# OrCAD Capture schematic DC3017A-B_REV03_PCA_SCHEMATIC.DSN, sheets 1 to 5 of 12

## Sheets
1 POWER SUPPLY: size Custom; company: ANALOG DEVICES; note: DEMO BOARD BILL OF MATERIALS; note: 24-PORT IEEE 802.3bt PSE MOTHER BOARD
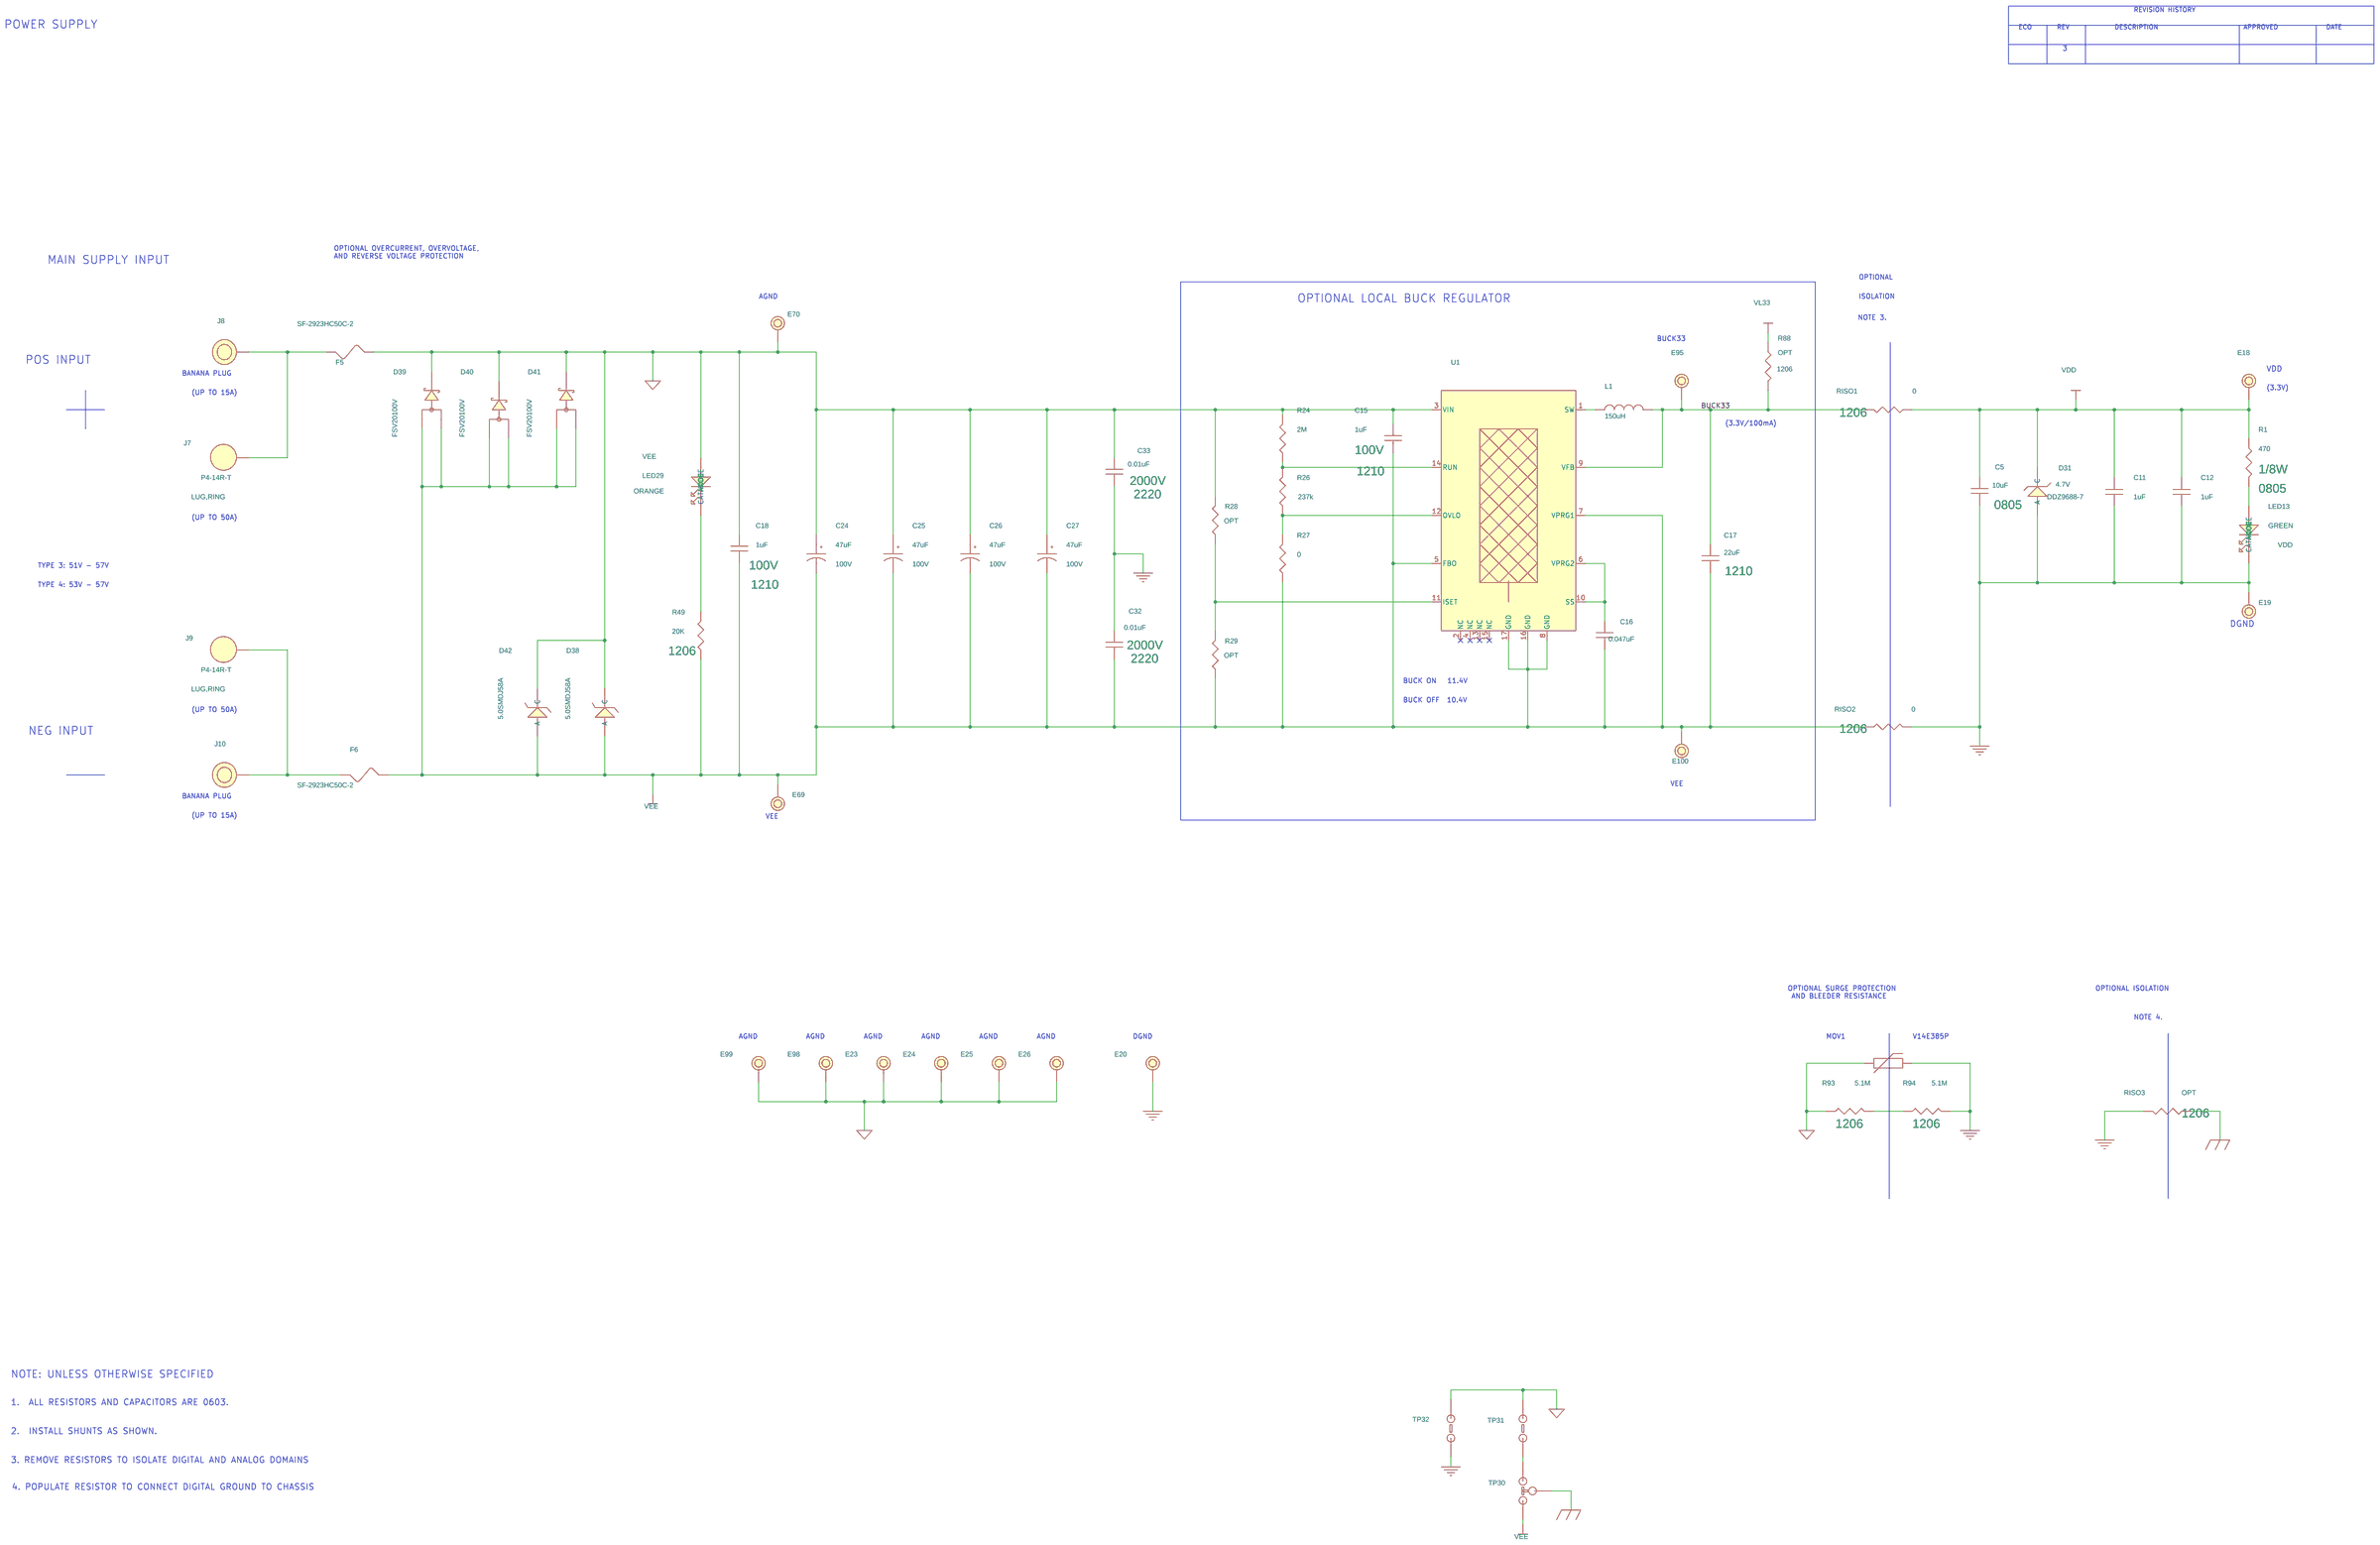
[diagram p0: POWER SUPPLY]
2 CONFIGURATIONS: size Custom
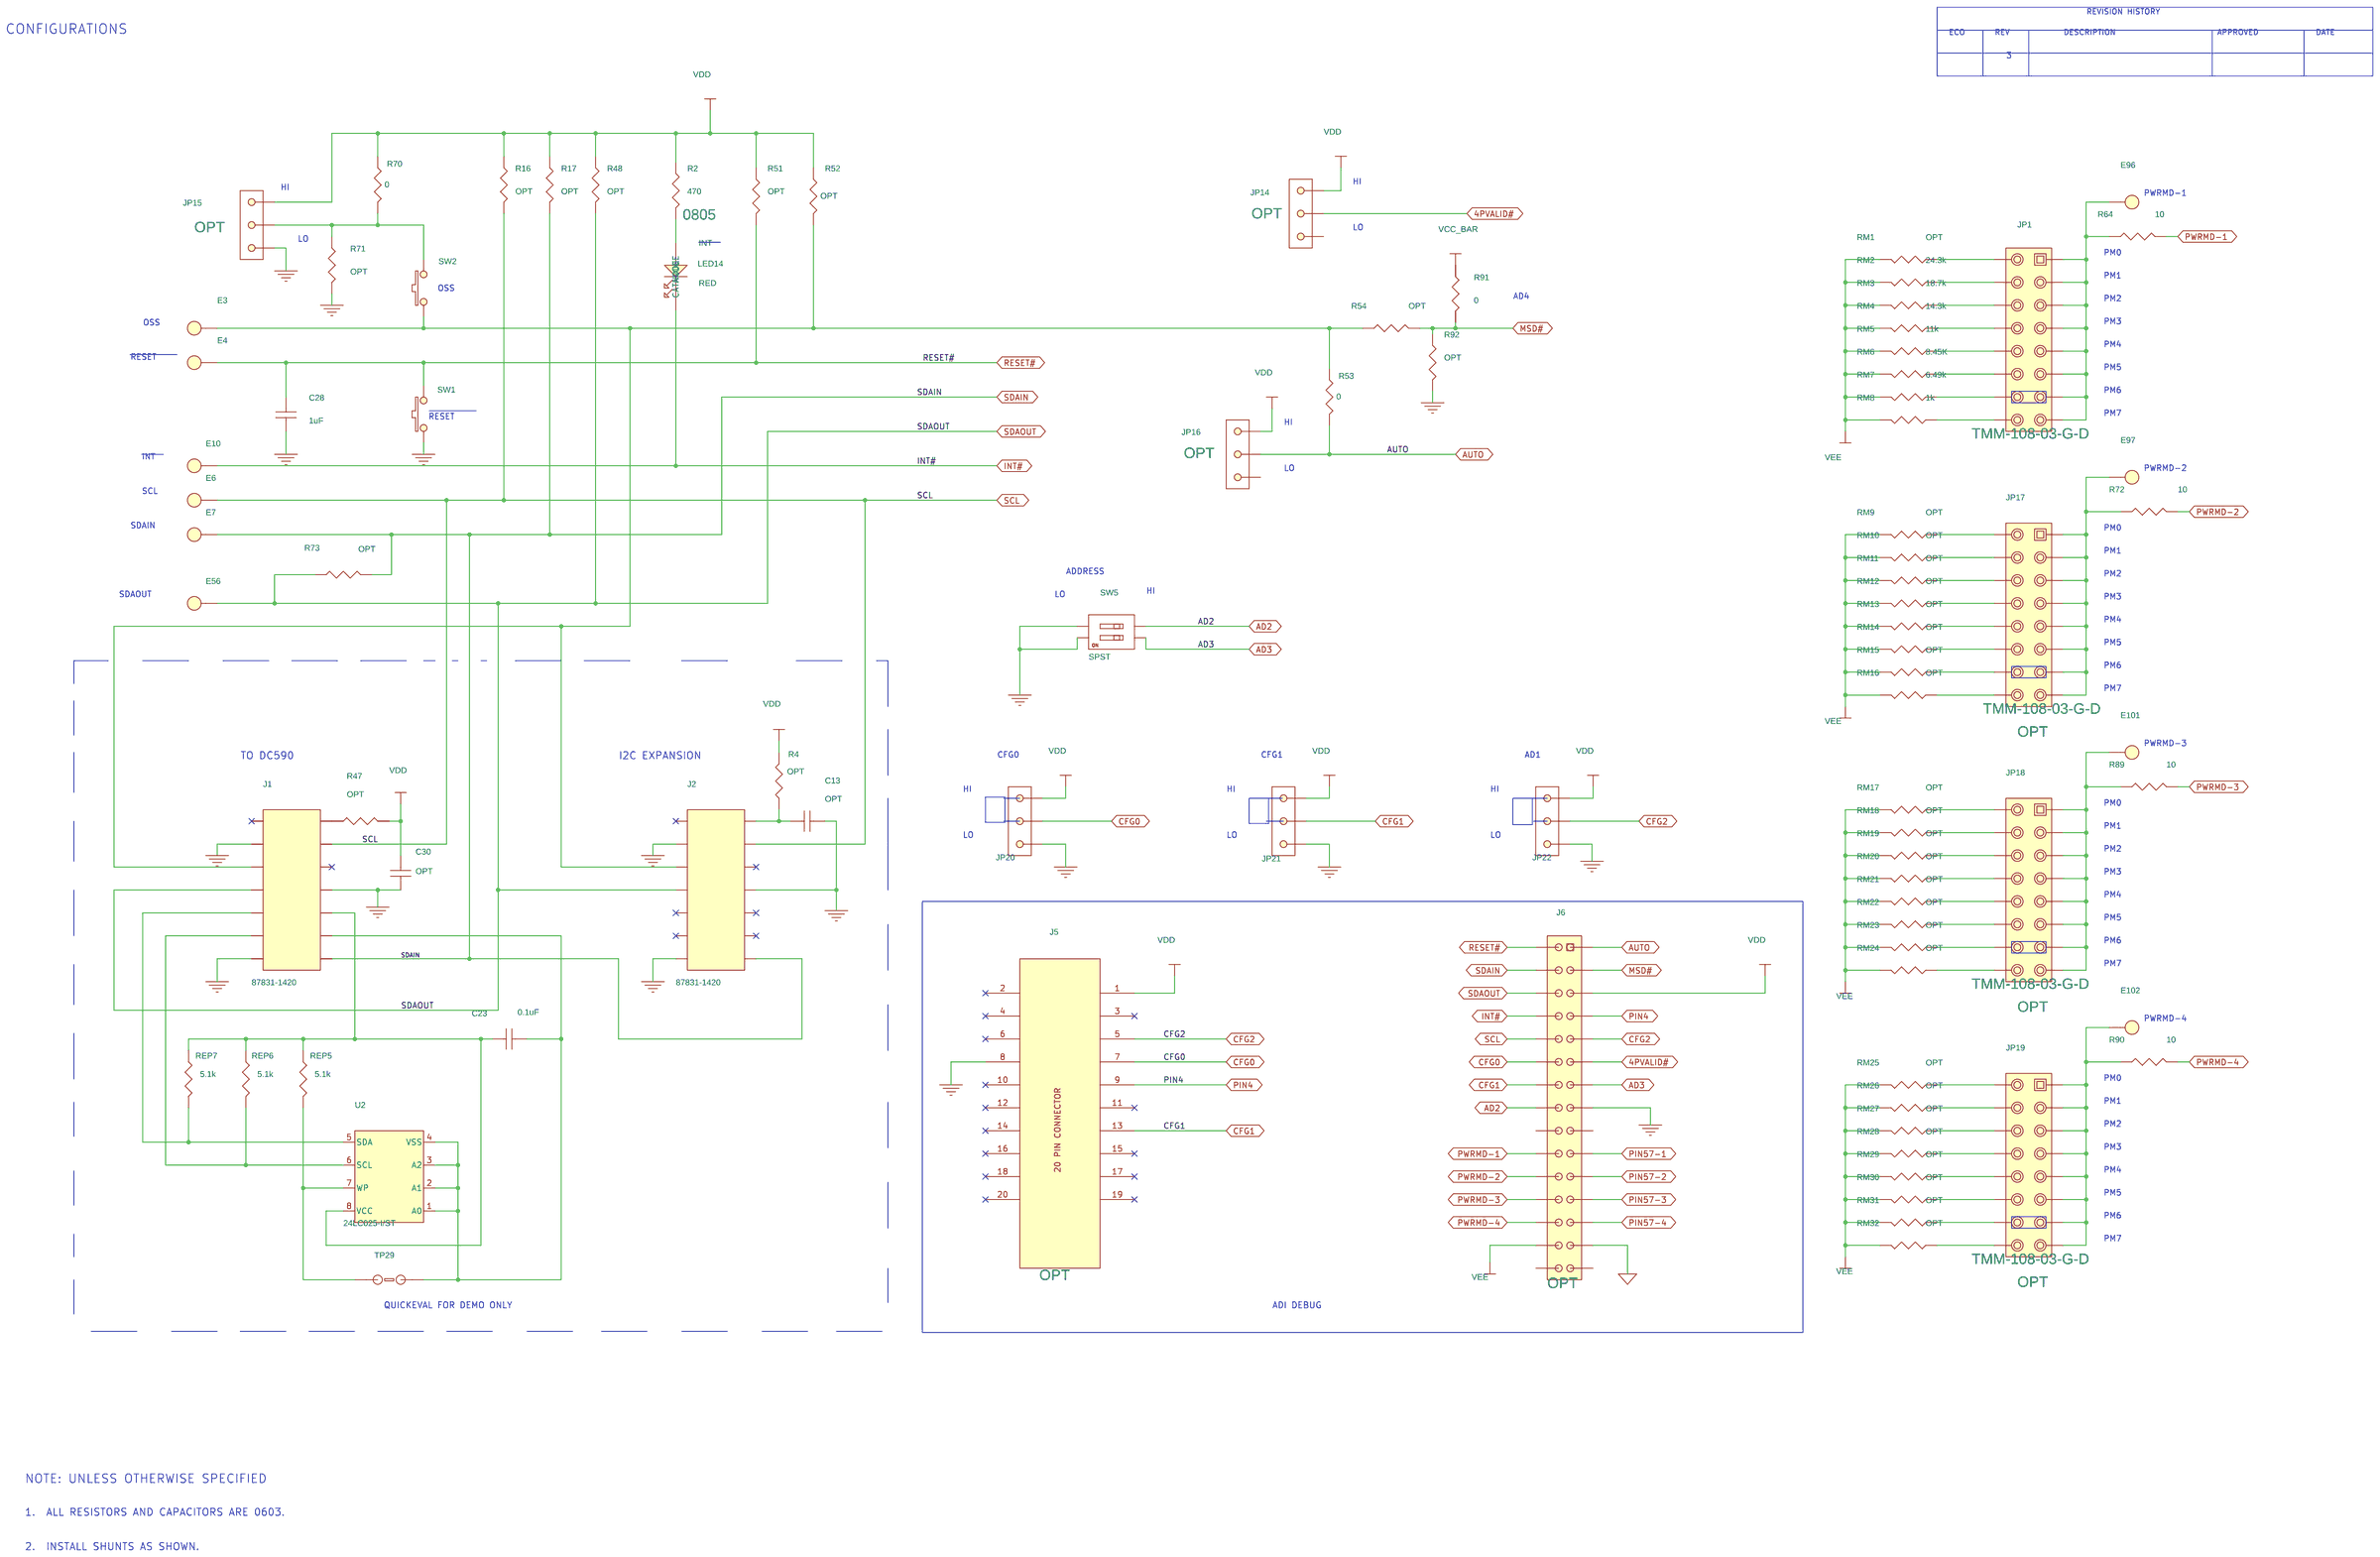
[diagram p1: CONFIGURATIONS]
3 DAUGHTER CARD CONNECTIONS: size Custom
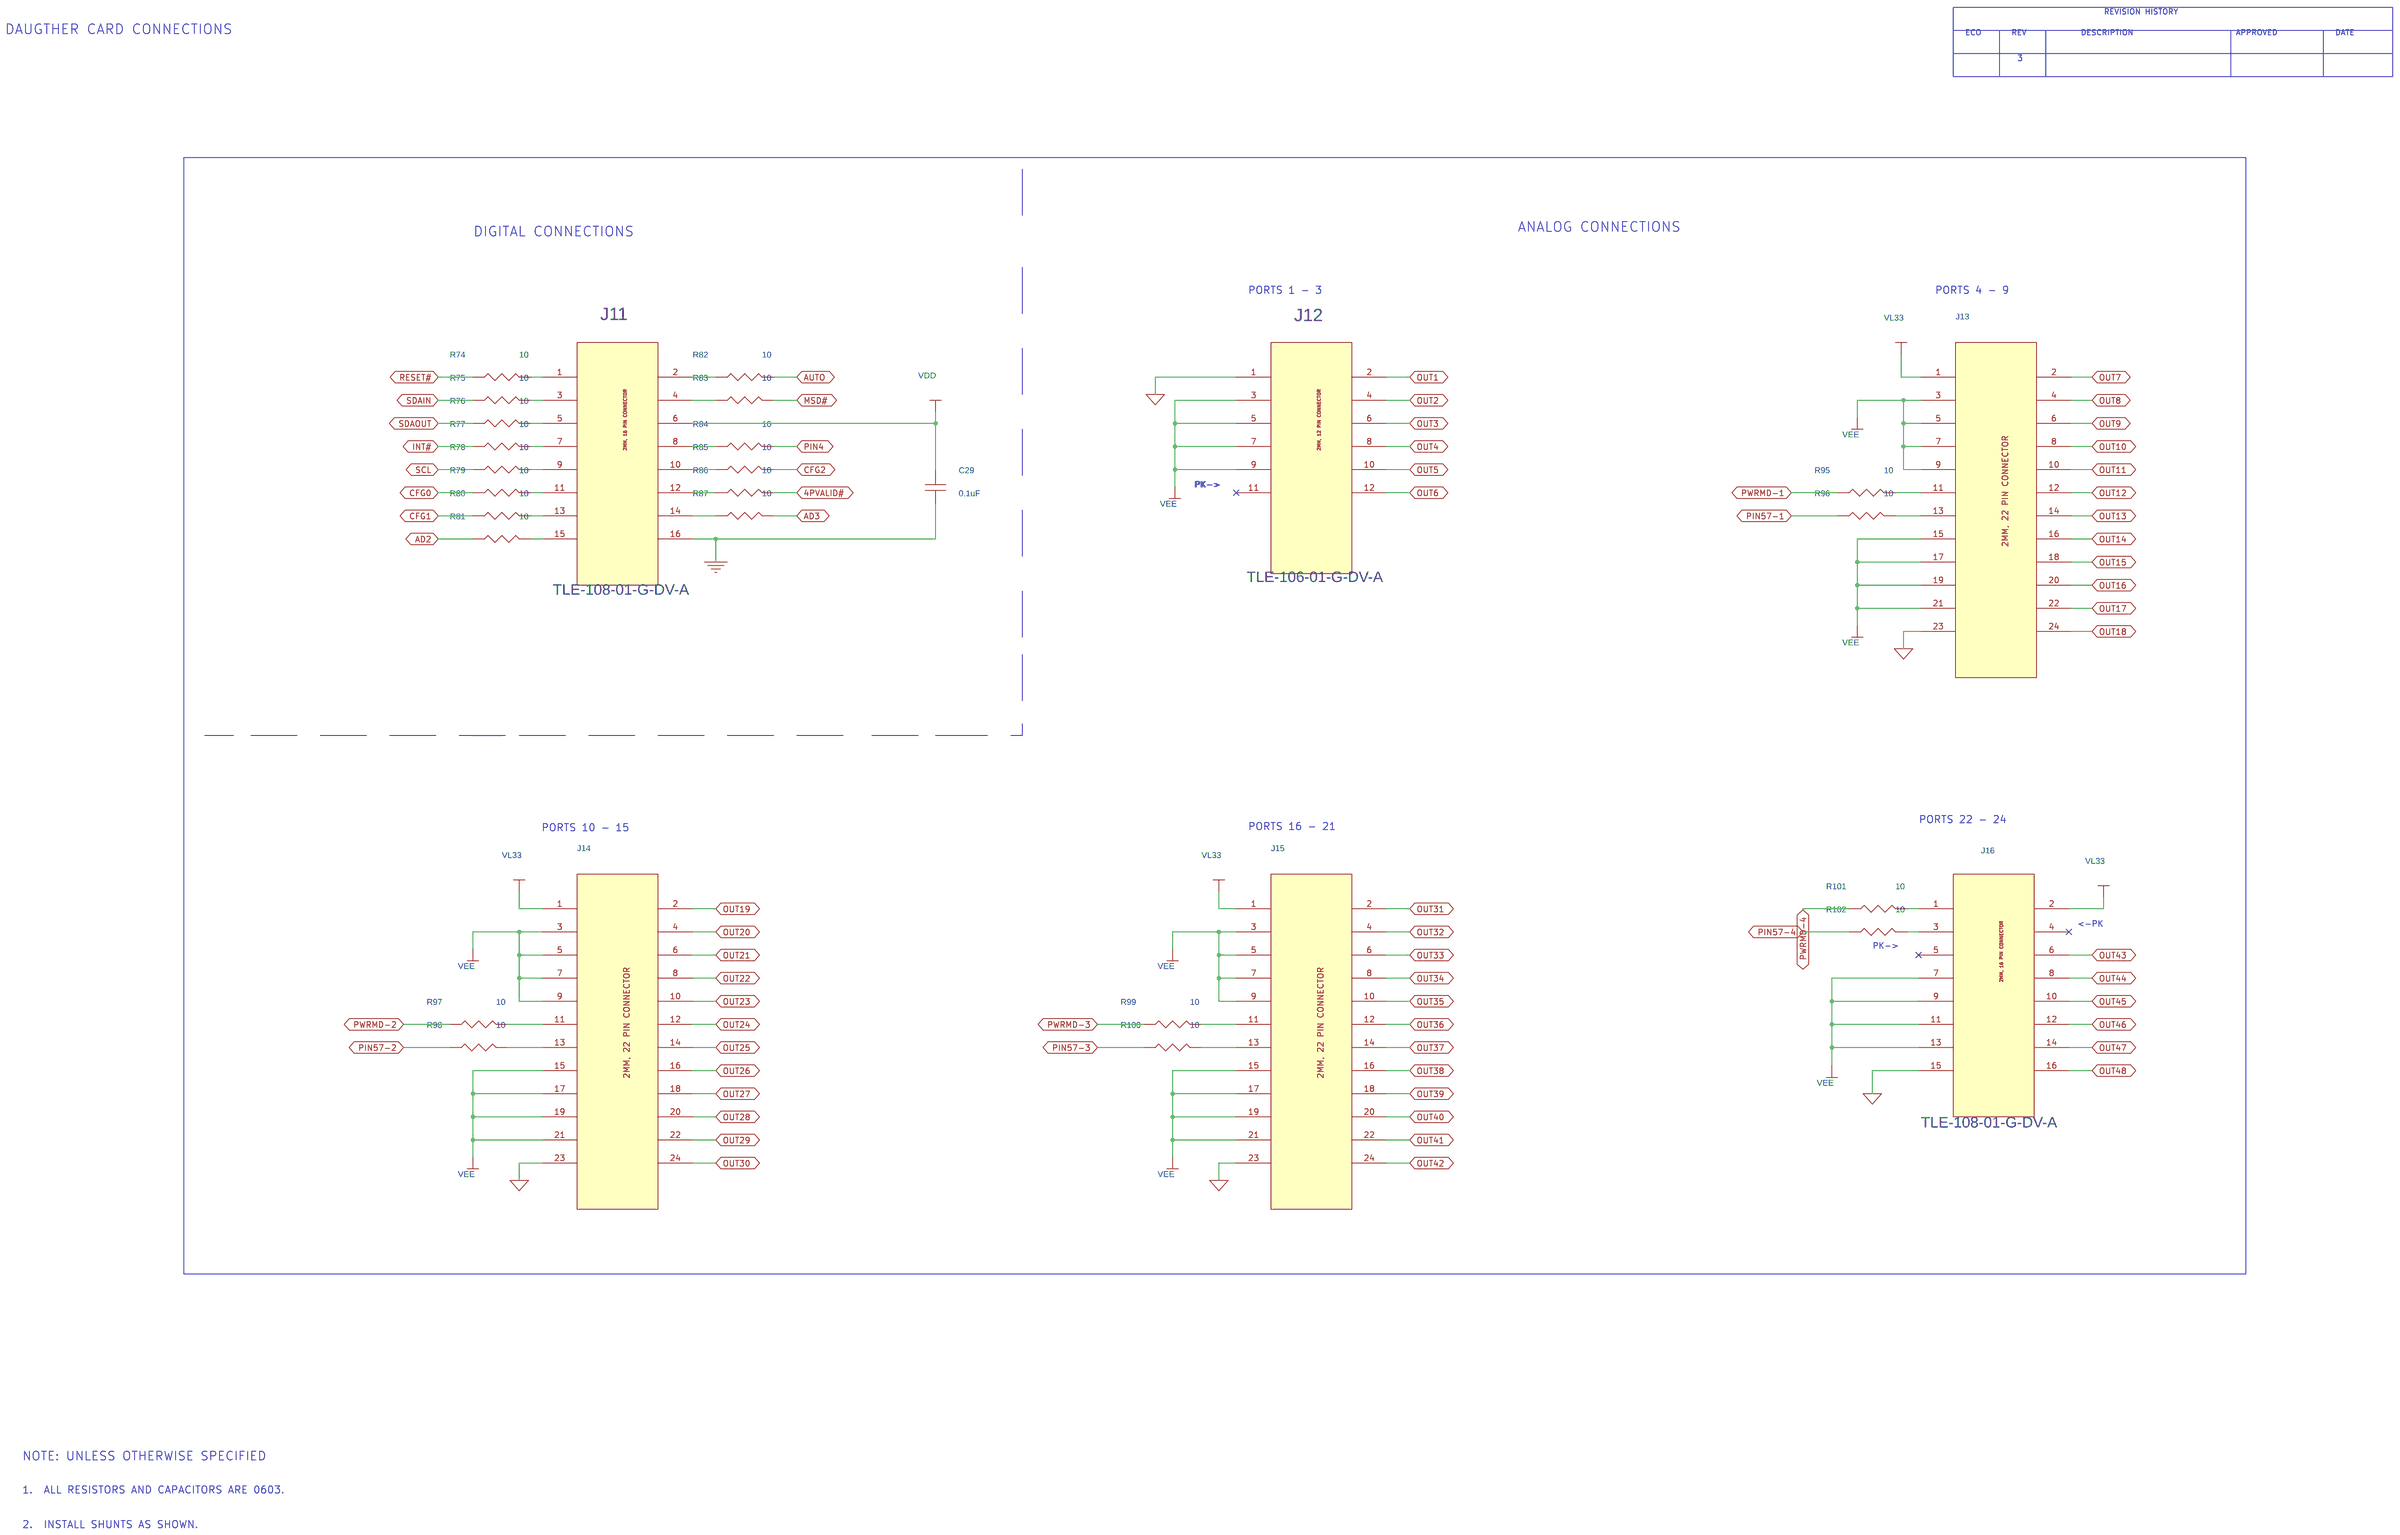
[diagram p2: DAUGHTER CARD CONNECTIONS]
4 PORTS 1-4: size Custom
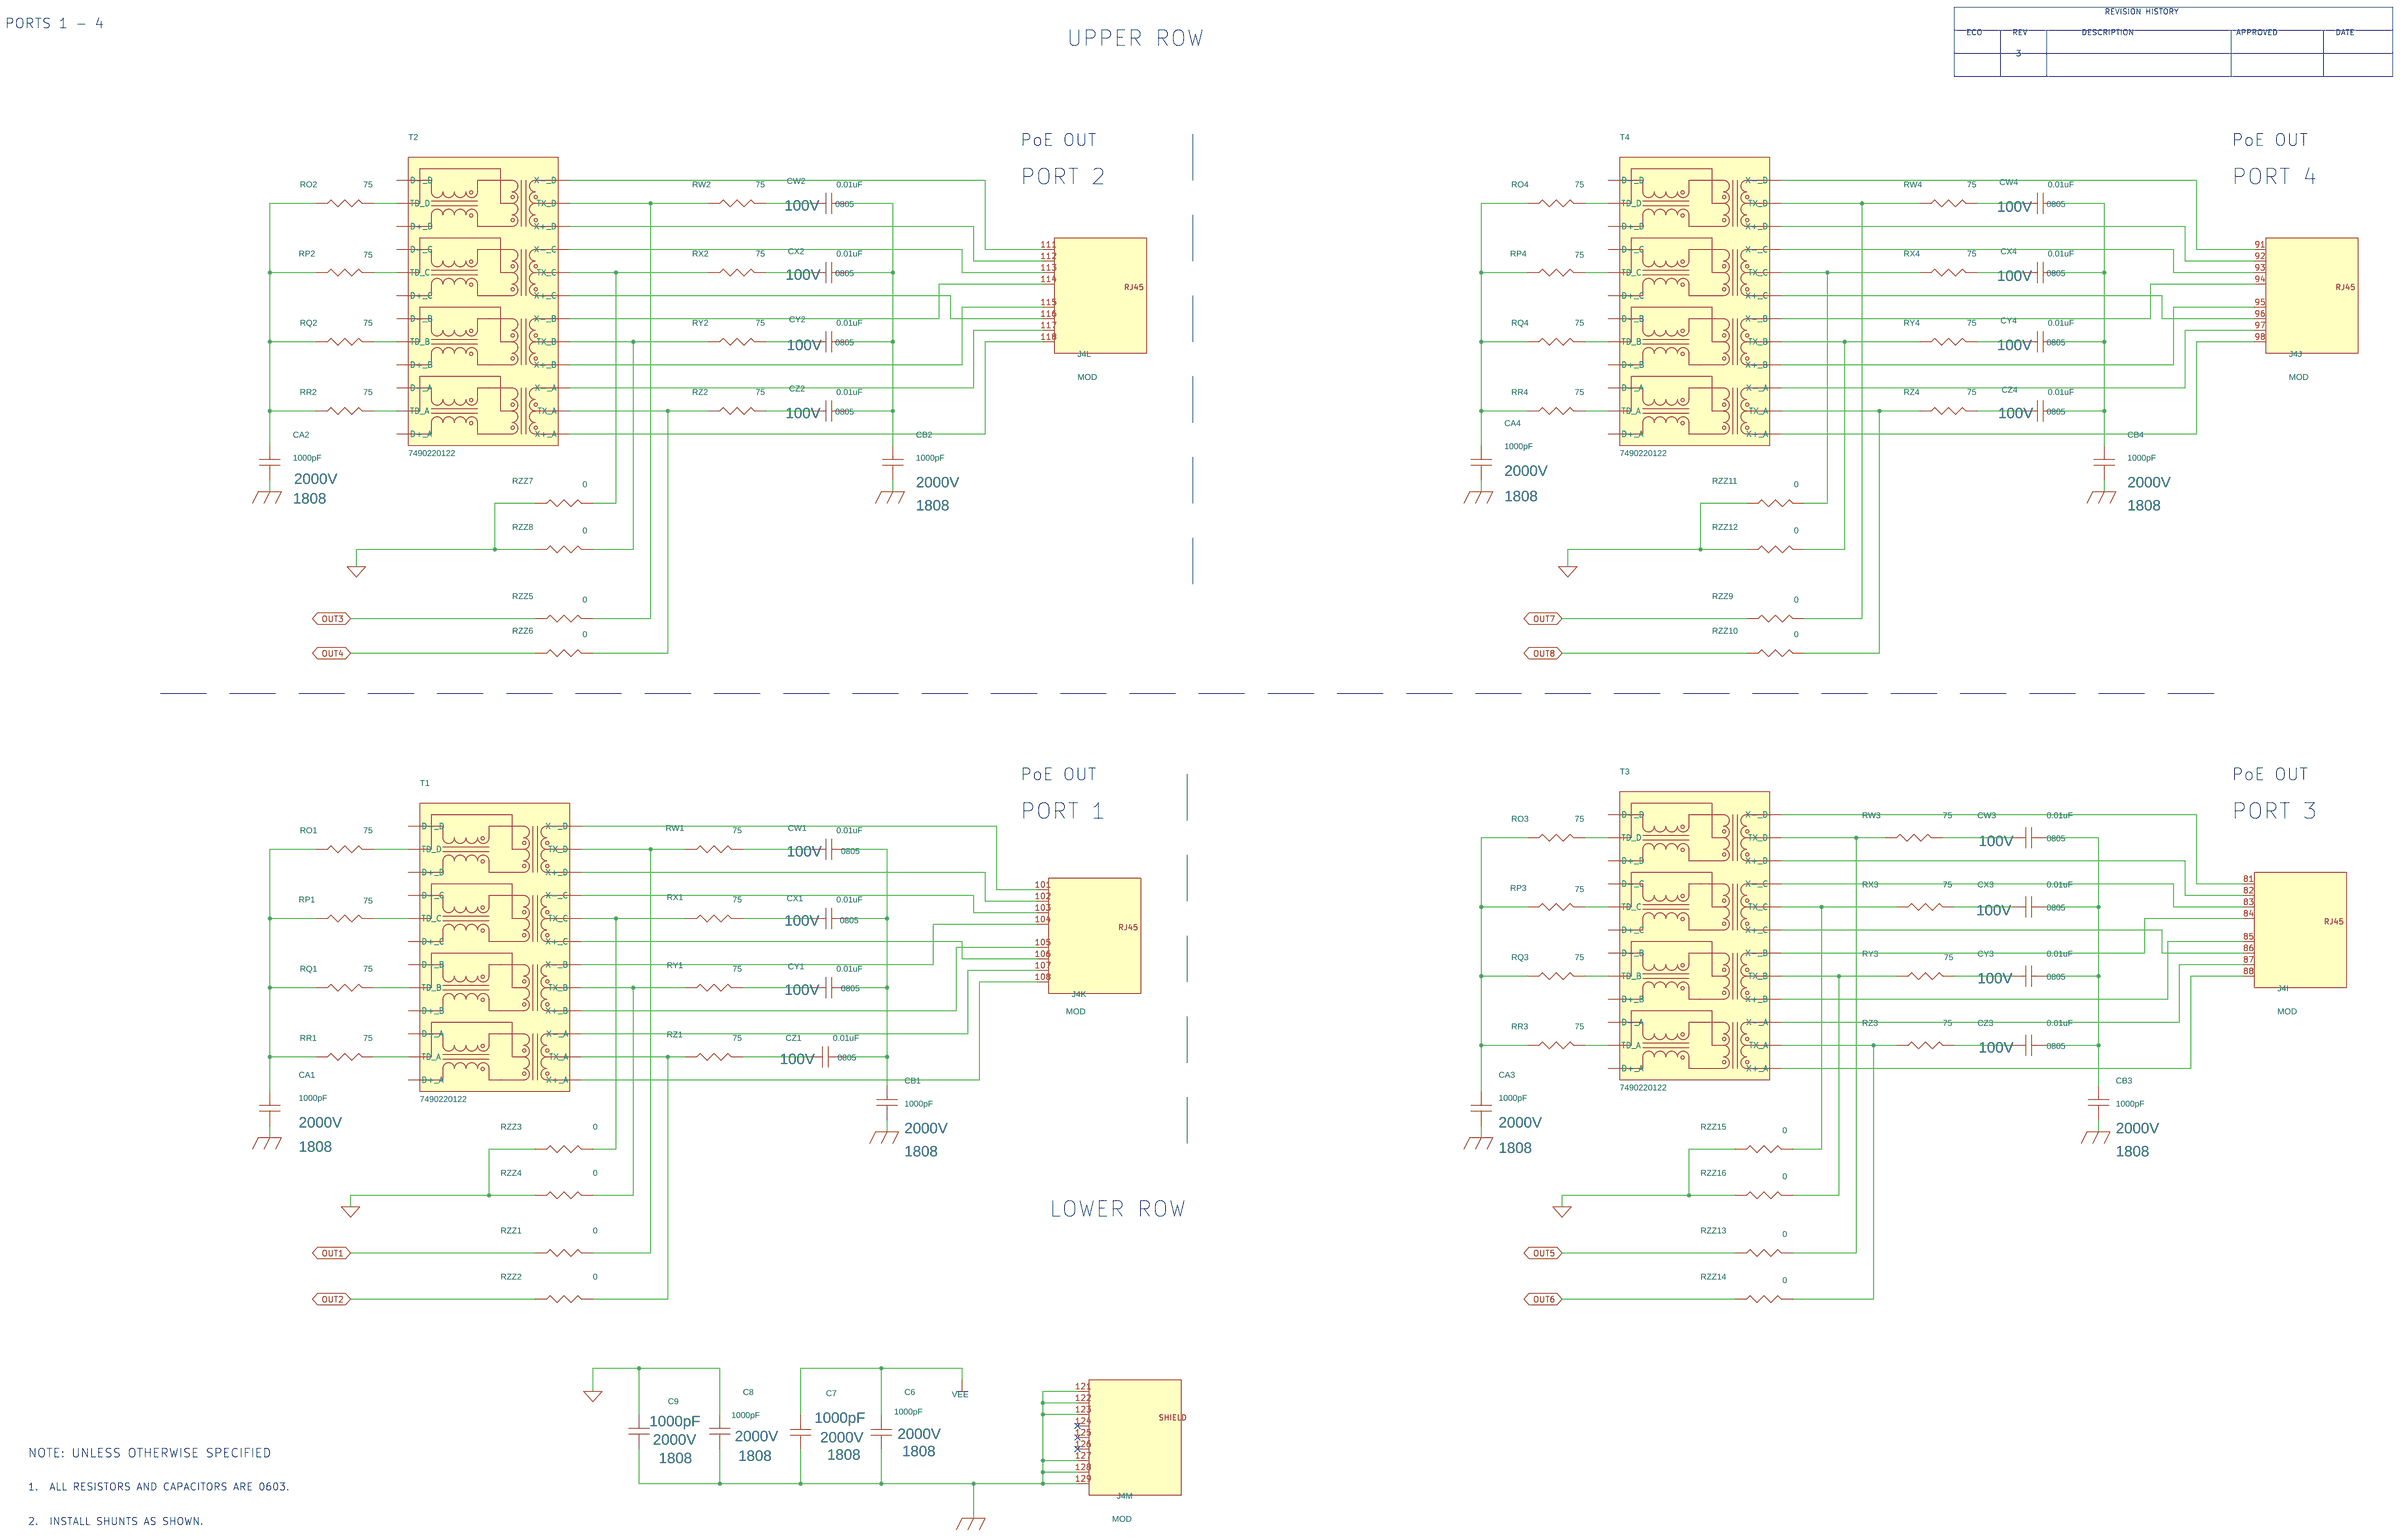
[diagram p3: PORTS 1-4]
5 PORTS 5-8: size Custom
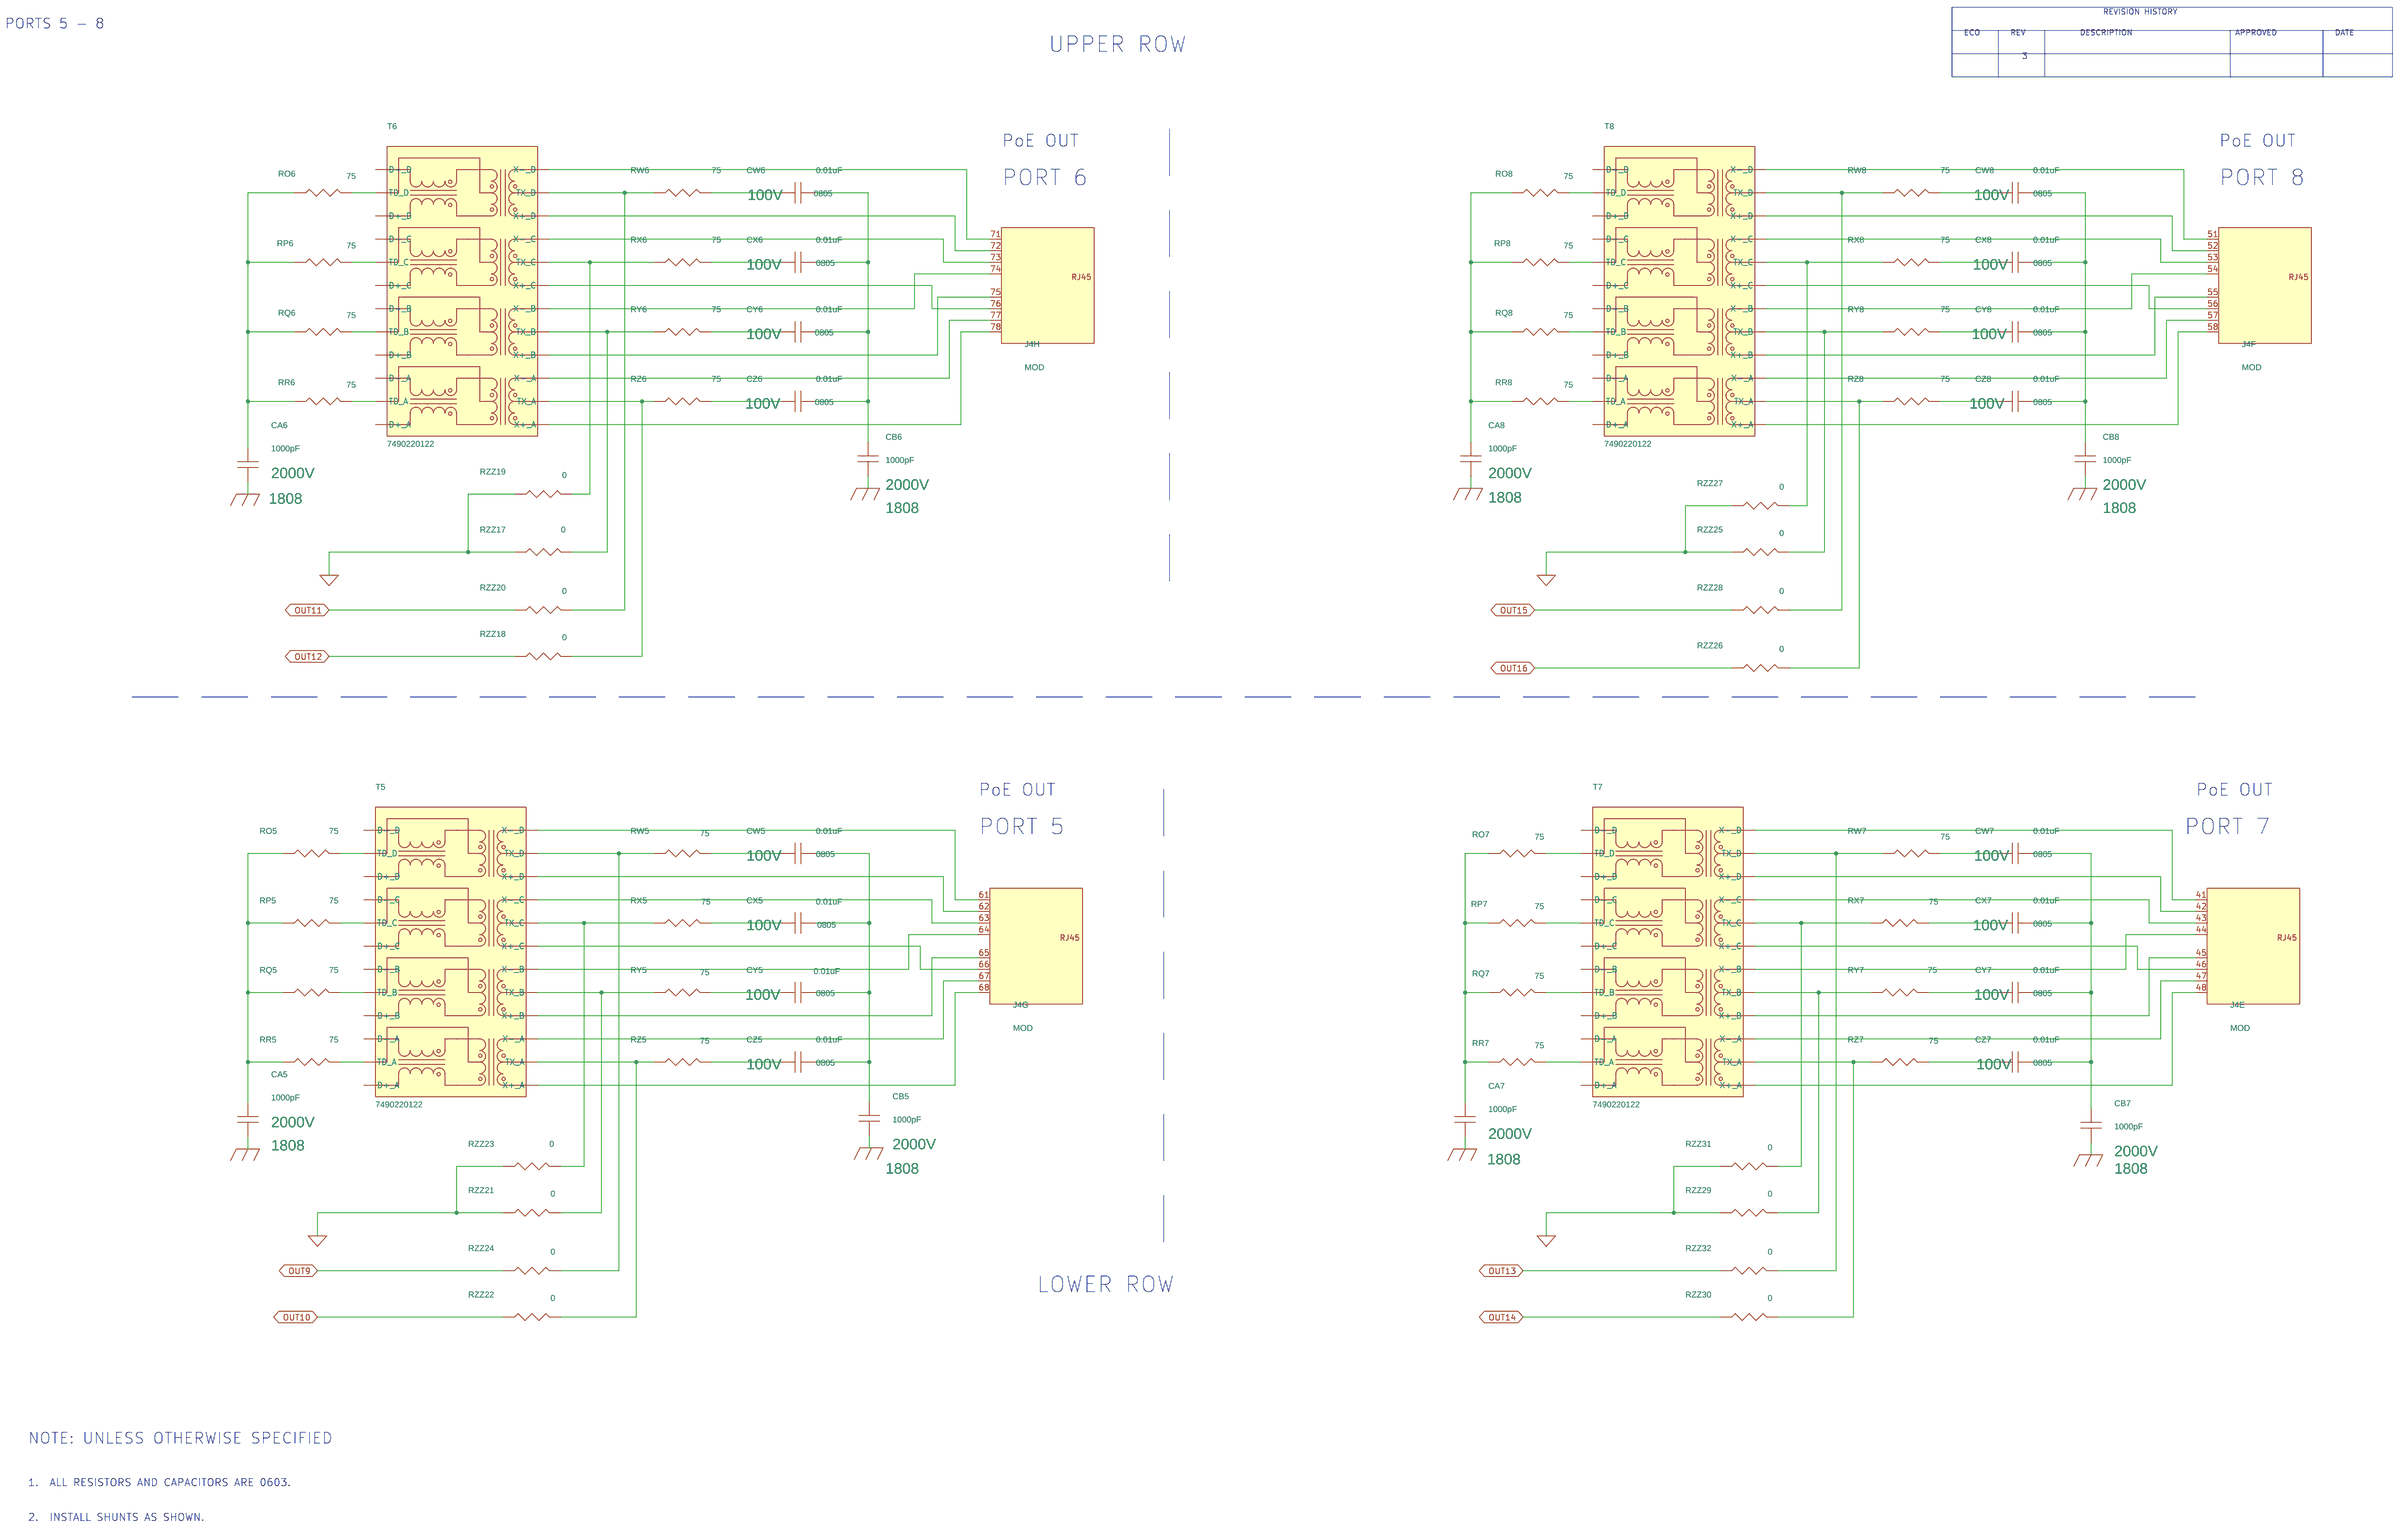
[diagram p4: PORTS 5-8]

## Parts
sheet CONFIGURATIONS
C13  OPT  [CC0603N]
C23  0.1uF  [CC0603N]
C28  1uF  [CC0603N]
C30  OPT  [CC0603N]
E3  TEST POINT  [MILLMAX2308]
E4  TEST POINT  [MILLMAX2308]
E6  TEST POINT  [MILLMAX2308]
E7  TEST POINT  [MILLMAX2308]
E10  TEST POINT  [MILLMAX2308]
E56  TEST POINT  [MILLMAX2308]
E96  TEST POINT  [MILLMAX2308]
E97  TEST POINT  [MILLMAX2308]
E101  TEST POINT  [MILLMAX2308]
E102  TEST POINT  [MILLMAX2308]
J1  HDR,SHROUDED  [MOLEX-87831-1420]
J2  HDR,SHROUDED  [MOLEX-87831-1420]
J5  HDR,SHROUDED  [WURTH-61202021721]
J6  HDR,SHROUDED  [SAMTEC_TSW-115-07-L-D]
JP1  HDR  [HD2X8-079]
JP14  HDR  [HD1X3-079]
JP15  HDR  [HD1X3-079]
JP16  HDR  [HD1X3-079]
JP17  HDR  [HD2X8-079]
JP18  HDR  [HD2X8-079]
JP19  HDR  [HD2X8-079]
JP20  HDR  [HD1X3-079]
JP21  HDR  [HD1X3-079]
JP22  HDR  [HD1X3-079]
LED14  RED  [LED_1208]
R2  470  [CR08050N]
R4  OPT  [CR0603N]
R16  OPT  [CR0603N]
R17  OPT  [CR0603N]
R47  OPT  [CR0603N]
R48  OPT  [CR0603N]
R51  OPT  [CR0603N]
R52  OPT  [CR0603N]
R53  0  [CR0603N]
R54  OPT  [CR0603N]
R64  10  [CR0603N]
R70  0  [CR0603N]
R71  OPT  [CR0603N]
R72  10  [CR0603N]
R73  OPT  [CR0603N]
R89  10  [CR0603N]
R90  10  [CR0603N]
R91  0  [CR0603N]
R92  OPT  [CR0603N]
REP5  5.1k  [CR0603N]
REP6  5.1k  [CR0603N]
REP7  5.1k  [CR0603N]
RM1  OPT  [CR0603N]
RM2  24.3k  [CR0603N]
RM3  18.7k  [CR0603N]
RM4  14.3k  [CR0603N]
RM5  11k  [CR0603N]
RM6  8.45K  [CR0603N]
RM7  6.49k  [CR0603N]
RM8  1k  [CR0603N]
RM9  OPT  [CR0603N]
RM10  OPT  [CR0603N]
RM11  OPT  [CR0603N]
RM12  OPT  [CR0603N]
RM13  OPT  [CR0603N]
RM14  OPT  [CR0603N]
RM15  OPT  [CR0603N]
RM16  OPT  [CR0603N]
RM17  OPT  [CR0603N]
RM18  OPT  [CR0603N]
RM19  OPT  [CR0603N]
RM20  OPT  [CR0603N]
RM21  OPT  [CR0603N]
RM22  OPT  [CR0603N]
RM23  OPT  [CR0603N]
RM24  OPT  [CR0603N]
RM25  OPT  [CR0603N]
RM26  OPT  [CR0603N]
RM27  OPT  [CR0603N]
RM28  OPT  [CR0603N]
RM29  OPT  [CR0603N]
RM30  OPT  [CR0603N]
RM31  OPT  [CR0603N]
RM32  OPT  [CR0603N]
SW1  SPST  [PANASONIC-EVQPE105K]
SW2  SPST  [PANASONIC-EVQPE105K]
SW5  SPST  [CTS-219-2]
TP29  SMD 2 pads  [testpad-2smd]
U2  24LC025-I/ST  [MO-153AA_N]
sheet DAUGHTER CARD CONNECTIONS
C29  0.1uF  [CC0603N]
J11  HDR,SOCKET STRIP  [SAMTEC-TLE-108-01-G-DV-A]
J12  HDR,SOCKET STRIP  [SAMTEC-TLE-106-01-G-DV-A]
J13  HDR,SOCKET STRIP  [SAMTEC-TLE-112-01-G-DV-A]
J14  HDR,SOCKET STRIP  [SAMTEC-TLE-112-01-G-DV-A]
J15  HDR,SOCKET STRIP  [SAMTEC-TLE-112-01-G-DV-A]
J16  HDR,SOCKET STRIP  [SAMTEC-TLE-108-01-G-DV-A]
R74  10  [CR0603N]
R75  10  [CR0603N]
R76  10  [CR0603N]
R77  10  [CR0603N]
R78  10  [CR0603N]
R79  10  [CR0603N]
R80  10  [CR0603N]
R81  10  [CR0603N]
R82  10  [CR0603N]
R83  10  [CR0603N]
R84  10  [CR0603N]
R85  10  [CR0603N]
R86  10  [CR0603N]
R87  10  [CR0603N]
R95  10  [CR0603N]
R96  10  [CR0603N]
R97  10  [CR0603N]
R98  10  [CR0603N]
R99  10  [CR0603N]
R100  10  [CR0603N]
R101  10  [CR0603N]
R102  10  [CR0603N]
sheet PORTS 1-4
C6  1000pF  [CC1808N]
C7  1000pF  [CC1808N]
C8  1000pF  [CC1808N]
C9  1000pF  [CC1808N]
CA1  1000pF  [CC1808N]
CA2  1000pF  [CC1808N]
CA3  1000pF  [CC1808N]
CA4  1000pF  [CC1808N]
CB1  1000pF  [CC1808N]
CB2  1000pF  [CC1808N]
CB3  1000pF  [CC1808N]
CB4  1000pF  [CC1808N]
CW1  0.01uF  [CC0805N]
CW2  0.01uF  [CC0805N]
CW3  0.01uF  [CC0805N]
CW4  0.01uF  [CC0805N]
CX1  0.01uF  [CC0805N]
CX2  0.01uF  [CC0805N]
CX3  0.01uF  [CC0805N]
CX4  0.01uF  [CC0805N]
CY1  0.01uF  [CC0805N]
CY2  0.01uF  [CC0805N]
CY3  0.01uF  [CC0805N]
CY4  0.01uF  [CC0805N]
CZ1  0.01uF  [CC0805N]
CZ2  0.01uF  [CC0805N]
CZ3  0.01uF  [CC0805N]
CZ4  0.01uF  [CC0805N]
J4  MOD  [STEWART-SS73100-046F]  (sections A,B,C,D,E,F,G,H,I,J,K,L,M)
RO1  75  [CR0603N]
RO2  75  [CR0603N]
RO3  75  [CR0603N]
RO4  75  [CR0603N]
RP1  75  [CR0603N]
RP2  75  [CR0603N]
RP3  75  [CR0603N]
RP4  75  [CR0603N]
RQ1  75  [CR0603N]
RQ2  75  [CR0603N]
RQ3  75  [CR0603N]
RQ4  75  [CR0603N]
RR1  75  [CR0603N]
RR2  75  [CR0603N]
RR3  75  [CR0603N]
RR4  75  [CR0603N]
RW1  75  [CR0603N]
RW2  75  [CR0603N]
RW3  75  [CR0603N]
RW4  75  [CR0603N]
RX1  75  [CR0603N]
RX2  75  [CR0603N]
RX3  75  [CR0603N]
RX4  75  [CR0603N]
RY1  75  [CR0603N]
RY2  75  [CR0603N]
RY3  75  [CR0603N]
RY4  75  [CR0603N]
RZ1  75  [CR0603N]
RZ2  75  [CR0603N]
RZ3  75  [CR0603N]
RZ4  75  [CR0603N]
RZZ1  0  [CR0603N]
RZZ2  0  [CR0603N]
RZZ3  0  [CR0603N]
RZZ4  0  [CR0603N]
RZZ5  0  [CR0603N]
RZZ6  0  [CR0603N]
RZZ7  0  [CR0603N]
RZZ8  0  [CR0603N]
RZZ9  0  [CR0603N]
RZZ10  0  [CR0603N]
RZZ11  0  [CR0603N]
RZZ12  0  [CR0603N]
RZZ13  0  [CR0603N]
RZZ14  0  [CR0603N]
RZZ15  0  [CR0603N]
RZZ16  0  [CR0603N]
T1  7490220122  [WURTH-7490220122]
T2  7490220122  [WURTH-7490220122]
T3  7490220122  [WURTH-7490220122]
T4  7490220122  [WURTH-7490220122]
sheet PORTS 5-8
CA5  1000pF  [CC1808N]
CA6  1000pF  [CC1808N]
CA7  1000pF  [CC1808N]
CA8  1000pF  [CC1808N]
CB5  1000pF  [CC1808N]
CB6  1000pF  [CC1808N]
CB7  1000pF  [CC1808N]
CB8  1000pF  [CC1808N]
CW5  0.01uF  [CC0805N]
CW6  0.01uF  [CC0805N]
CW7  0.01uF  [CC0805N]
CW8  0.01uF  [CC0805N]
CX5  0.01uF  [CC0805N]
CX6  0.01uF  [CC0805N]
CX7  0.01uF  [CC0805N]
CX8  0.01uF  [CC0805N]
CY5  0.01uF  [CC0805N]
CY6  0.01uF  [CC0805N]
CY7  0.01uF  [CC0805N]
CY8  0.01uF  [CC0805N]
CZ5  0.01uF  [CC0805N]
CZ6  0.01uF  [CC0805N]
CZ7  0.01uF  [CC0805N]
CZ8  0.01uF  [CC0805N]
RO5  75  [CR0603N]
RO6  75  [CR0603N]
RO7  75  [CR0603N]
RO8  75  [CR0603N]
RP5  75  [CR0603N]
RP6  75  [CR0603N]
RP7  75  [CR0603N]
RP8  75  [CR0603N]
RQ5  75  [CR0603N]
RQ6  75  [CR0603N]
RQ7  75  [CR0603N]
RQ8  75  [CR0603N]
RR5  75  [CR0603N]
RR6  75  [CR0603N]
RR7  75  [CR0603N]
RR8  75  [CR0603N]
RW5  75  [CR0603N]
RW6  75  [CR0603N]
RW7  75  [CR0603N]
RW8  75  [CR0603N]
RX5  75  [CR0603N]
RX6  75  [CR0603N]
RX7  75  [CR0603N]
RX8  75  [CR0603N]
RY5  75  [CR0603N]
RY6  75  [CR0603N]
RY7  75  [CR0603N]
RY8  75  [CR0603N]
RZ5  75  [CR0603N]
RZ6  75  [CR0603N]
RZ7  75  [CR0603N]
RZ8  75  [CR0603N]
RZZ17  0  [CR0603N]
RZZ18  0  [CR0603N]
RZZ19  0  [CR0603N]
RZZ20  0  [CR0603N]
RZZ21  0  [CR0603N]
RZZ22  0  [CR0603N]
RZZ23  0  [CR0603N]
RZZ24  0  [CR0603N]
RZZ25  0  [CR0603N]
RZZ26  0  [CR0603N]
RZZ27  0  [CR0603N]
RZZ28  0  [CR0603N]
RZZ29  0  [CR0603N]
RZZ30  0  [CR0603N]
RZZ31  0  [CR0603N]
RZZ32  0  [CR0603N]
T5  7490220122  [WURTH-7490220122]
T6  7490220122  [WURTH-7490220122]
T7  7490220122  [WURTH-7490220122]
T8  7490220122  [WURTH-7490220122]
sheet POWER SUPPLY
C5  10uF  [CC0805N]
C11  1uF  [CC0603N]
C12  1uF  [CC0603N]
C15  1uF  [CC1210N]
C16  0.047uF  [CC0603N]
C17  22uF  [CC1210N]
C18  1uF  [CC1210N]
C24  47uF  [PANASONIC_FKV_12.5X13.5]
C25  47uF  [PANASONIC_FKV_12.5X13.5]
C26  47uF  [PANASONIC_FKV_12.5X13.5]
C27  47uF  [PANASONIC_FKV_12.5X13.5]
C32  0.01uF  [CC2220N]
C33  0.01uF  [CC2220N]
D31  DDZ9688-7  [SOD-123N]
D38  5.0SMDJ58A  [SMC-N]
D39  FSV20100V  [ONSEMI-TO-277_340BQ]
D40  FSV20100V  [ONSEMI-TO-277_340BQ]
D41  FSV20100V  [ONSEMI-TO-277_340BQ]
D42  5.0SMDJ58A  [SMC-N]
E18  TEST POINT  [MILLMAX2501]
E19  TEST POINT  [MILLMAX2501]
E20  TEST POINT  [MILLMAX2501]
E23  TEST POINT  [MILLMAX2501]
E24  TEST POINT  [MILLMAX2501]
E25  TEST POINT  [MILLMAX2501]
E26  TEST POINT  [MILLMAX2501]
E69  TEST POINT  [MILLMAX2501]
E70  TEST POINT  [MILLMAX2501]
E95  TEST POINT  [MILLMAX2501]
E98  TEST POINT  [MILLMAX2501]
E99  TEST POINT  [MILLMAX2501]
E100  TEST POINT  [MILLMAX2501]
F5  FUSE,CER.,SINGLFUSE  [BOURNS-SF-2923HC-C]
F6  FUSE,CER.,SINGLFUSE  [BOURNS-SF-2923HC-C]
J7  LUG,RING  [PANDUIT-P4-14R-T]
J8  BANANA JACK  [KEY-575-4]
J9  LUG,RING  [PANDUIT-P4-14R-T]
J10  BANANA JACK  [KEY-575-4]
L1  150uH  [COILCRAFT-LPS6235]
LED13  GREEN  [LED_1208]
LED29  ORANGE  [LED_1208]
MOV1  VARISTOR,385VAC/505VDC  [LITTELFUSE-VARISTOR14MM]
R1  470  [CR08050N]
R24  2M  [CR0603N]
R26  237k  [CR0603N]
R27  0  [CR0603N]
R28  OPT  [CR0603N]
R29  OPT  [CR0603N]
R49  20K  [CR1206N]
R88  OPT  [CR1206N]
R93  5.1M  [CR1206N]
R94  5.1M  [CR1206N]
RISO1  0  [CR1206N]
RISO2  0  [CR1206N]
RISO3  OPT  [CR1206N]
TP30  SMD 2 pads  [TEST_3PINS]
TP31  0  [testpad-2smd]
TP32  0  [TP20mm]
U1  LTC3639EMSE  [LTC-MSE-16-1871]

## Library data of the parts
C13 C30 = CAP: CAP., OPTION, 0603; CLASS: DISCRETE; FPLIST: CC0603N,CC0603L,CC0603M; PART_NUMBER: 150-3038; Package Size: 0603; Package Type: SMD
C23 C29 = CAP: CAP.,0.1uF,X7R,10V,10%,0603; CLASS: DISCRETE; Dielectric Type: X7R; FPLIST: CC0603N,CC0603L,CC0603M; Inventory Qty: 24592; Manufacturer: AVX; Manufacturer PN: 0603ZC104KAT2A; PART_NUMBER: 150-3176; Package Size: 0603; Rated Voltage: 10V; Tolerance: 10%
C11 C12 C28 = CAP: CAP.,1uF,X5R,16V,10%,0603; CLASS: DISCRETE; Dielectric Type: X5R; FPLIST: CC0603N,CC0603L,CC0603M; Inventory Qty: 10506; Manufacturer: AVX; Manufacturer PN: 0603YD105KAT2A; PART_NUMBER: 150-0110; Package Size: 0603; Rated Voltage: 16V; Tolerance: 10%
E3 E4 E6 E7 E10 E56 E96 E97 E101 E102 = TEST_POINT_.156_MILL-MAX_2308: TEST POINT,TURRET,0.064" MTG. HOLE,PCB 0.125" THK; CLASS: IO; FPLIST: MILLMAX2308,MILLMAX2308-4; Inventory Qty: 25153; Manufacturer: MILL-MAX; Manufacturer PN: 2308-4-00-80-00-00-07-0; PART_NUMBER: 260-0008
J1 J2 = DC590_ALT6: CONN.,HDR,SHROUDED,PLUG,MALE,2x7,2mm,VERT,ST,THT,KEYED; CLASS: IO; FPLIST: MOLEX-87831-1420,HD2X7-079-MOLEX; Inventory Qty: 4800; Manufacturer: MOLEX; Manufacturer PN: 87831-1420; PART_NUMBER: 250-0790
J5 = 61202021721: CONN.,HDR,SHROUDED,MALE,2x10,2.54mm,R/A,THT; CLASS: IO; DNI: OPT; Inventory Qty: 988; Manufacturer: WURTH ELEKTRONIK; PART_NUMBER: 250-0962
J6 = TSW-115-07-L-D: CONN.,HDR,SHROUDED,MALE,2x15,2.54mm,VERT,ST,THT; CLASS: IO; DNI: OPT; Inventory Qty: 0; Manufacturer: SAMTEC; PART_NUMBER: 250-1022
JP1 = HDR2X8_ALT1: CONN.,HDR,MALE,2x8,2mm,VERT,ST,THT,GOLD; CLASS: IO; Inventory Qty: 1178; Manufacturer: SAMTEC; Manufacturer PN: TMM-108-03-G-D; PART_NUMBER: 250-0969
JP14 JP16 = 3_PIN_HEADER_.079_SINGLE_ROW_C: CONN.,HDR,MALE,1x3,2mm,VERT,ST,THT; BOM Notes: OPT; CLASS: IO; Inventory Qty: 22026; Manufacturer: Wurth Elektronik; Manufacturer PN: 62000311121; PART_NUMBER: 250-0484
JP15 = 3_PIN_HEADER_.079_SINGLE_ROW_C: CONN.,HDR,MALE,1x3,2mm,VERT,ST,THT; BOM NOTES: OPT; CLASS: IO; Inventory Qty: 22026; Manufacturer: Wurth Elektronik; Manufacturer PN: 62000311121; PART_NUMBER: 250-0484
JP17-JP19 = HDR2X8_ALT1: CONN.,HDR,MALE,2x8,2mm,VERT,ST,THT,GOLD; 7th Part Field: OPT; BOM Notes: NOT STUFF; CLASS: IO; DNI: NO STUFF; Inventory Qty: 1178; Manufacturer: SAMTEC; Manufacturer PN: TMM-108-03-G-D; PART_NUMBER: 250-0969
JP20-JP22 = 3_PIN_HEADER_.079_SINGLE_ROW_C: CONN.,HDR,MALE,1x3,2mm,VERT,ST,THT; CLASS: IO; Inventory Qty: 22026; Manufacturer: Wurth Elektronik; Manufacturer PN: 62000311121; PART_NUMBER: 250-0484
LED14 = LED: LED,RED,CLEAR,3020 (1208); CLASS: DISCRETE; Inventory Qty: 32837; Manufacturer: ROHM; Manufacturer PN: SML-012V8TT86; PART FIELD 1: INT; PART_NUMBER: 270-0077; Package Type: 3020 (1208)
R1 R2 = RES: RES.,470 OHMS,5%,1/8W,0805,AEC-Q200; 2ND PART FIELD: 0805; 4TH PART FIELD: VISHAY,; CLASS: DISCRETE; FPLIST: CR08050N,CR0805L,CR0805M; Inventory Qty: 9952; Manufacturer: NIC; Manufacturer PN: NRC10J471TRF; PART_NUMBER: 100-1563; Package Size: 0805; Rated Power: 1/8W; Temperature Coefficient: +/-200ppm; Tolerance: 5%
R4 R16 R17 R48 R51 R52 R54 R71 R73 R92 RM1 RM9 RM17 RM25 = RES: RES., OPTION, 0603; CLASS: DISCRETE; FPLIST: CR0603N,CR0603L,CR0603M; PART_NUMBER: 100-2374; Package Size: 0603
R47 = RES: RES., OPTION, 0603; CLASS: DISCRETE; FPLIST: CR0603N,CR0603L,CR0603M; PART_NUMBER: 100-2374; Package Size: 0603; Part Number: VISHAY CRCW06031R00JNEA
R53 R70 = RES: RES.,0 OHM,1/10W,0603,AEC-Q200; CLASS: DISCRETE; FPLIST: CR0603N,CR0603L,CR0603M; Inventory Qty: 676258; Manufacturer: VISHAY; Manufacturer PN: CRCW06030000Z0EA; OPT: OPT; PART_NUMBER: 100-0009; Package Size: 0603; Rated Power: 1/10W
R64 R72 R74-R87 R89 R90 R95-R102 = RES: RES.,10 OHMS,5%,1/10W,0603,AEC-Q200; CLASS: DISCRETE; FPLIST: CR0603N,CR0603L,CR0603M; Inventory Qty: 87608; Manufacturer: VISHAY; Manufacturer PN: CRCW060310R0JNEA; PART_NUMBER: 100-2744; Package Size: 0603; Rated Power: 1/10W; Temperature Coefficient: +/-200ppm; Tolerance: 5%
R91 = RES: RES.,0 OHM,1/10W,0603,AEC-Q200; CLASS: DISCRETE; FPLIST: CR0603N,CR0603L,CR0603M; Inventory Qty: 676258; Manufacturer: VISHAY; Manufacturer PN: CRCW06030000Z0EA; PART_NUMBER: 100-0009; Package Size: 0603; Rated Power: 1/10W
REP5-REP7 = RES: RES.,5.1k OHMS,1%,1/10W,0603,AEC-Q200; CLASS: DISCRETE; FPLIST: CR0603N,CR0603L,CR0603M; Inventory Qty: 33794; Manufacturer: NIC; Manufacturer PN: NRC06F5101TRF; PART_NUMBER: 100-0491; Package Size: 0603; Rated Power: 1/10W; Temperature Coefficient: 100ppm; Tolerance: 1%
RM2 = RES: RES.,24.3k OHMS,1%,1/10W,0603,AEC-Q200; CLASS: DISCRETE; FPLIST: CR0603N,CR0603L,CR0603M; Inventory Qty: 3832; Manufacturer: VISHAY; Manufacturer PN: CRCW060324K3FKEA; PART_NUMBER: 100-0614; Package Size: 0603; Rated Power: 1/10W; Size: 0805; Temperature Coefficient: 100ppm; Tolerance: 1%
RM3 = RES: RES.,18.7k OHMS,1%,1/10W,0603,AEC-Q200; CLASS: DISCRETE; FPLIST: CR0603N,CR0603L,CR0603M; Inventory Qty: 69830; Manufacturer: NIC; Manufacturer PN: NRC06F1872TRF; PART_NUMBER: 100-0666; Package Size: 0603; Rated Power: 1/10W; Size: 0805; Temperature Coefficient: 100ppm; Tolerance: 1%
RM4 = RES: RES.,14.3k OHMS,1%,1/10W,0603,AEC-Q200; CLASS: DISCRETE; FPLIST: CR0603N,CR0603L,CR0603M; Inventory Qty: 10000; Manufacturer: PANASONIC; Manufacturer PN: ERJ3EKF1432V; PART_NUMBER: 100-1075; Package Size: 0603; Rated Power: 1/10W; Size: 0805; Temperature Coefficient: +/-100ppm; Tolerance: 1%
RM5 = RES: RES.,11k OHMS,1%,1/10W,0603,AEC-Q200; CLASS: DISCRETE; FPLIST: CR0603N,CR0603L,CR0603M; Inventory Qty: 10354; Manufacturer: PANASONIC; Manufacturer PN: ERJ3EKF1102V; PART_NUMBER: 100-0066; Package Size: 0603; Rated Power: 1/10W; Size: 0805; Temperature Coefficient: 100ppm/C; Tolerance: 1%
RM6 = RES: RES.,8.45k OHMS,1%,1/10W,0603,AEC-Q200; CLASS: DISCRETE; FPLIST: CR0603N,CR0603L,CR0603M; Inventory Qty: 50756; Manufacturer: NIC; Manufacturer PN: NRC06F8451TRF; PART_NUMBER: 100-0866; Package Size: 0603; Rated Power: 1/10W; Size: 0805; Temperature Coefficient: +/-100PPM; Tolerance: 1%
RM7 = RES: RES.,6.49k OHMS,1%,1/10W,0603; CLASS: DISCRETE; FPLIST: CR0603N,CR0603L,CR0603M; Inventory Qty: 35566; Manufacturer: VISHAY; Manufacturer PN: CRCW06036K49FKEA; PART_NUMBER: 100-2793; Package Size: 0603; Rated Power: 1/10W; Size: 0805; Temperature Coefficient: 100ppm/C; Tolerance: 1%
RM8 = RES: RES.,1k OHM,1%,1/10W,0603; CLASS: DISCRETE; FPLIST: CR0603N,CR0603L,CR0603M; Inventory Qty: 62420; Manufacturer: VISHAY; Manufacturer PN: CRCW06031K00FKEA; PART_NUMBER: 100-0136; Package Size: 0603; Rated Power: 1/10W; Size: 0805; Temperature Coefficient: +/-100ppm; Tolerance: 1%
RM10-RM16 RM18-RM24 RM26-RM32 = RES: RES., OPTION, 0603; CLASS: DISCRETE; FPLIST: CR0603N,CR0603L,CR0603M; PART_NUMBER: 100-2374; Package Size: 0603; Size: 0805
SW1 SW2 = SW_PUSHBUTTON: SWITCH,LT,TACTILE,SPST,0.05A,12V,J-BENT,SMD,6.0x3.5mm,5mm H,BLK; CLASS: DISCRETE; Inventory Qty: 3700; Manufacturer: PANASONIC; Manufacturer PN: EVQPE105K; PART_NUMBER: 430-0062
SW5 = DIP_SW_2POS: SWITCH,SLIDE,DIP,SPST,100mA,20VDC,SMD,GULL WING,2 POS,MEDIUM ACTUATOR,TOP TAPE SEAL; CLASS: DISCRETE; Inventory Qty: 226; Manufacturer: CTS; Manufacturer PN: 219-2MST; PART_NUMBER: 430-1187
TP29 = testpad-2smd: SMD PADS; Part Number: NONE
U2 = 24LC025-I_ST_TSSOP-8: IC, MEMORY,EEPROM,2Kb (256x8),TSSOP-8,400kHz; CLASS: IC; FPLIST: MO-153AA_N,MO-153AA_L,MO-153AA_M,MICROCHIP-TSSOP-8; Inventory Qty: 19510; Manufacturer: Microchip; PART_NUMBER: 380-0087; Package Size: TSSOP-8; Package Type: TSSOP-8
J11 J16 = TLE-108-01-G-DV-A: CONN.,HDR,SOCKET STRIP,RCPT,FEMALE,2x8,2mm,VERT,ST,SMT,GOLD; CLASS: IO; Inventory Qty: 152; Manufacturer: SAMTEC; PART_NUMBER: 250-0964
J12 = TLE-106-01-G-DV-A: CONN.,HDR,SOCKET STRIP,RCPT,FEMALE,2x6,2mm,VERT,ST,SMT,GOLD; CLASS: IO; Inventory Qty: 76; Manufacturer: SAMTEC; PART_NUMBER: 250-0965
J13-J15 = TLE-112-01-G-DV-A: CONN.,HDR,SOCKET STRIP,RCPT,FEMALE,2x12,2mm,VERT,ST,SMT,GOLD; CLASS: IO; Inventory Qty: 228; Manufacturer: SAMTEC; PART_NUMBER: 250-0966
C6-C9 CB1-CB8 = CAP: CAP.,1000pF,X7R,2000V,10%,1808; CLASS: DISCRETE; Dielectric Type: X7R; FPLIST: CC1808N,CC1808L,CC1808M; Inventory Qty: 13522; Manufacturer: KEMET; Manufacturer PN: C1808C102KGRACTU; PART_NUMBER: 150-3301; Package Size: 1808; Rated Voltage: 2000V; Tolerance: 10%
CA1-CA8 = CAP: CAP.,1000pF,X7R,2000V,10%,1808; CLASS: DISCRETE; Case Size: 1808; Dielectric Type: X7R; FPLIST: CC1808N,CC1808L,CC1808M; Inventory Qty: 13522; Manufacturer: KEMET; Manufacturer PN: C1808C102KGRACTU; PART_NUMBER: 150-3301; Package Size: 1808; Rated Voltage: 2000V; Tolerance: 10%
CW1-CW8 CX1-CX8 CY1-CY8 CZ1-CZ8 = CAP: CAP.,0.01uF,X7R,100V,10%,0805; 1ST PART FIELD: 0805; CLASS: DISCRETE; Dielectric Type: X7R; FPLIST: CC0805N,CC0805L,CC0805M; Inventory Qty: 51316; Manufacturer: AVX; Manufacturer PN: 08051C103KAT2A; PART_NUMBER: 150-2308; Package Size: 0805; Package Type: SMD; Part Number: AVX 0805C103JAT2A; Rated Voltage: 100V; Tolerance: 10%; VOLTAGE: 100V
J4 = RJ45-SS-73100-046F: CONN.,MOD,STACKJACK,12PORTS(2x6),8P8C,R/A,THT,RJ45,ETHERNET,SHIELDED,50u" Au; CLASS: IO; Inventory Qty: 620; Manufacturer: STEWART CONN./ BEL; Manufacturer PN: SS73100-046F; PART_NUMBER: 250-0961
RO1-RO8 RP1-RP8 RQ1-RQ8 RR1-RR8 RW1-RW8 RX1-RX8 RY1-RY8 RZ1-RZ8 = RES: RES.,75 OHMS,5%,1/10W,0603,AEC-Q200; CLASS: DISCRETE; FPLIST: CR0603N,CR0603L,CR0603M; Inventory Qty: 64896; Manufacturer: NIC; Manufacturer PN: NRC06J750TRF; PART_NUMBER: 100-0315; Package Size: 0603; Part Number: VISHAY CRCW060375R0JNEA; Rated Power: 1/10W; Temperature Coefficient: 200ppm/C; Tolerance: 5%
RZZ1-RZZ32 = RES: RES.,0 OHM,1/10W,0603,AEC-Q200; CLASS: DISCRETE; FPLIST: CR0603N,CR0603L,CR0603M; Inventory Qty: 676258; Manufacturer: VISHAY; Manufacturer PN: CRCW06030000Z0EA; PART_NUMBER: 100-0009; Package Size: 0603; Part Number: VISHAY CRCW060375R0JNEA; Rated Power: 1/10W
T1-T8 = WURTH-7490220122: XFMR,LAN,1CT:1CT Tx, 1CT:1CT Rx,350uH,SMD,1000 Base-T,4PPoE,1 PORT; CLASS: DISCRETE; Inventory Qty: 1124; Manufacturer: WURTH ELEKTRONIK; PART_NUMBER: 410-0123; Turns Ratio: 1CT:1CT Tx, 1CT:1CT Rx
C5 = CAP: CAP.,10uF,X7R,10V,10%,0805; CLASS: DISCRETE; Dielectric Type: X7R; FPLIST: CC0805N,CC0805L,CC0805M; Inventory Qty: 25564; Manufacturer: AVX; Manufacturer PN: 0805ZC106KAT2A; PART_NUMBER: 150-3001; Package Size: 0805; Rated Voltage: 10V; Tolerance: 10%
C15 = CAP: CAP.,1uF,X7R,100V,10%,1210; 1ST PART FIELD: 100V; CLASS: DISCRETE; Case Size: 1210; Dielectric Type: X7R; FPLIST: CC1210N,CC1210L,CC1210M; Inventory Qty: 7882; Manufacturer: AVX; Manufacturer PN: 12101C105KAT2A; PART_NUMBER: 150-3442; Package Size: 1210; Rated Voltage: 100V; Tolerance: 10%
C16 = CAP: CAP.,0.047uF,X7R,16V,10%,0603; CLASS: DISCRETE; Dielectric Type: X7R; FPLIST: CC0603N,CC0603L,CC0603M; Inventory Qty: 24676; Manufacturer: AVX; Manufacturer PN: 0603YC473KAT2A; PART_NUMBER: 150-3198; Package Size: 0603; Rated Voltage: 16V; Tolerance: 10%
C17 = CAP: CAP.,22uF,X5R,6.3V,20%,1210; 1ST PART FIELD: 100V; CLASS: DISCRETE; Dielectric Type: X5R; FPLIST: CC1210N,CC1210L,CC1210M; Inventory Qty: 3776; Manufacturer: AVX; Manufacturer PN: 12106D226MAT2A; PART_NUMBER: 150-0217; Package Size: 1210; Rated Voltage: 6.3V; Tolerance: 20%
C18 = CAP: CAP.,1uF,X7R,100V,10%,1210; 1ST PART FIELD: 100V; CLASS: DISCRETE; Dielectric Type: X7R; FPLIST: CC1210N,CC1210L,CC1210M; Inventory Qty: 7882; Manufacturer: AVX; Manufacturer PN: 12101C105KAT2A; PART_NUMBER: 150-3442; Package Size: 1210; Rated Voltage: 100V; Tolerance: 10%
C24-C27 = CAP_P: CAP.,47uF,ALUM,100V,20%,12.5x13.5mm,H13,RADIAL,SMD,AEC-Q200; CLASS: DISCRETE; Dielectric Type: ALUM; FPLIST: PANASONIC_FKV_12.5X13.5,PANASONIC_FKV_12-5X13-5; Inventory Qty: 1904; Manufacturer: PANASONIC; Manufacturer PN: EEVFK2A470Q; PART_NUMBER: 150-1557; Package Size: 12.5x13.5mm,H13,RADIAL,SMD; Package Type: Surface Mount; Rated Voltage: 100V; Tolerance: 20%
C32 C33 = CAP: CAP.,0.01uF,X7R,2000V,10%,2220; CLASS: DISCRETE; Dielectric Type: X7R; FPLIST: CC2220N,CC2220L,CC2220M; Inventory Qty: 2500; Manufacturer: KEMET; Manufacturer PN: C2220C103KGRACTU; PART_NUMBER: 150-0826; Package Size: 2220; Package Type: Surface Mount, MLCC; Rated Voltage: 2000V; Temperature Coefficient: X7R; Tolerance: 10%
D31 = ZENER: DIODE,ZENER,4.7V,500mW,SOD-123; CLASS: DISCRETE; FPLIST: SOD-123N,SOD-123L,SOD-123M; Inventory Qty: 1910; Manufacturer: DIODES INC.; PART_NUMBER: 210-0309; Package Size: SOD-123; Package Type: SOD-123; Rated Voltage or Zener Voltage: 4.7V
D38 D42 = DIODE_TVS_B: DIODE,TVS,UNI-DIR,58V,5kW,DO-214AB (SMC J-Bend); CLASS: DISCRETE; FPLIST: SMC-N,SMC-L,SMC-M; Inventory Qty: 476; Manufacturer: BOURNS; Max Forward Current or Rated Power: 200mW; PART_NUMBER: 210-0545; Package Type: DO-214AB (SMC J-Bend); Rated Voltage or Zener Voltage: 58V
D39-D41 = DIODE_SCHOTTKY_PACKAGE4: DIODE,SCHOTTKY,100V,20A,TO-277-3; CLASS: DISCRETE; Inventory Qty: 428; Manufacturer: ON SEMICONDUCTOR; PART_NUMBER: 210-0480; Package Type: TO-277-3; Rated Voltage or Zener Voltage: 100V
E18-E20 E23-E26 E69 E70 E95 E98-E100 = TESTPOINT_.219_MILL-MAX_2501: TEST POINT,TURRET,0.094" MTG. HOLE,PCB 0.062" THK; CLASS: IO; FPLIST: MILLMAX2501,MILLMAX2501-2; Inventory Qty: 823526; Manufacturer: MILL-MAX; Manufacturer PN: 2501-2-00-80-00-00-07-0; PART_NUMBER: 260-0003
F5 F6 = FUSE: FUSE,CER.,SINGLFUSE,50A,60VDC,J-LEAD,2-SMD,2923; CLASS: DISCRETE; Inventory Qty: 0; Manufacturer: BOURNS; Manufacturer PN: SF-2923HC50C-2; PART_NUMBER: 120-0076; Rated Current: 50A; Rated Voltage: 60V
J7 J9 = STUD_3: LUG,RING,1/4" STUD,CRIMP,4 AWG,1.40" L,NON-INSULATED; CLASS: DISCRETE; Inventory Qty: 0; Manufacturer: PANDUIT; Manufacturer PN: P4-14R-T; PART_FIELD_01: <PART_FIELD_01>; PART_FIELD_02: <PART_FIELD_02>; PART_NUMBER: 769-0022
J8 J10 = BANANA_KEYSTONE-575-4: CONN.,BANANA JACK,FEMALE,THT,NON-INSULATED,SWAGE,0.218"; CLASS: IO; Inventory Qty: 203061; Manufacturer: KEYSTONE; Manufacturer PN: 575-4; PART_NUMBER: 250-0428
L1 = IND: IND.,150uH,PWR,SHIELDED,20%,730mA,535mOHMS,6.08x6.08mm,AEC-Q200; CLASS: DISCRETE; Inventory Qty: 176; Manufacturer: COILCRAFT; Manufacturer PN: LPS6235-154MRC; PART_NUMBER: 200-0766; Package Size: 6.08x6.08mm; Tolerance: 20%
LED13 = LED: LED,GREEN,CLEAR,3020 (1208); CLASS: DISCRETE; Inventory Qty: 31807; Manufacturer: ROHM; Manufacturer PN: SML-012P8TT86; PART FIELD 1: VDD; PART_NUMBER: 270-0075; Package Type: 3020 (1208); Size: 1208
LED29 = LED: LED,ORANGE,CLEAR,3020 (1208); CLASS: DISCRETE; Inventory Qty: 18151; Manufacturer: ROHM; Manufacturer PN: SML-012D8TT86; PART FIELD 1: VEE; PART_NUMBER: 270-0074; Package Type: 3020 (1208)
MOV1 = VARISTOR: RES.,VARISTOR,385VAC/505VDC,6kA,RADIAL,THT,DISC,14mm,EPOXY,METAL-OXIDE; CLASS: DISCRETE; Inventory Qty: 0; Manufacturer: LITTELFUSE; Manufacturer PN: V14E385P; PART_NUMBER: 103-0040; Package Size: RADIAL,THT,DISC,14mm; Rated Power: 6kA
R24 = RES: RES.,2M OHMS,5%,1/10W,0603,AEC-Q200; 2ND PART FIELD: 0603; 4TH PART FIELD: VISHAY,; CLASS: DISCRETE; FPLIST: CR0603N,CR0603L,CR0603M; Inventory Qty: 13176; Manufacturer: KOA SPEER; Manufacturer PN: RK73B1JTTD205J; PART_NUMBER: 100-0223; Package Size: 0603; Rated Power: 1/10W; Temperature Coefficient: 200ppm/C; Tolerance: 5%
R26 = RES: RES.,237k OHMS,1%,1/10W,0603; CLASS: DISCRETE; FPLIST: CR0603N,CR0603L,CR0603M; Inventory Qty: 9988; Manufacturer: NIC; Manufacturer PN: NRC06F2373TRF; PART_NUMBER: 100-2578; Package Size: 0603; Rated Power: 1/10W; Temperature Coefficient: 100ppm/C; Tolerance: 1%
R27 = RES: RES.,0 OHM,1/10W,0603,AEC-Q200; 2ND PART FIELD: 0603; 4TH PART FIELD: VISHAY,; CLASS: DISCRETE; FPLIST: CR0603N,CR0603L,CR0603M; Inventory Qty: 676258; Manufacturer: VISHAY; Manufacturer PN: CRCW06030000Z0EA; PART_NUMBER: 100-0009; Package Size: 0603; Rated Power: 1/10W
R28 R29 = RES: RES., OPTION, 0603; 2ND PART FIELD: 0603; 4TH PART FIELD: VISHAY,; CLASS: DISCRETE; FPLIST: CR0603N,CR0603L,CR0603M; PART_NUMBER: 100-2374; Package Size: 0603
R49 = RES: RES.,20k OHMS,1%,1/4W,1206,AEC-Q200; 2ND PART FIELD: 0805; 4TH PART FIELD: VISHAY,; CLASS: DISCRETE; Case Size: 1206; FPLIST: CR1206N,CR1206L,CR1206M; Inventory Qty: 28804; Manufacturer: PANASONIC; Manufacturer PN: ERJ8ENF2002V; PART_NUMBER: 100-0607; Package Size: 1206; Rated Power: 1/4W; Temperature Coefficient: 100PPM; Tolerance: 1%
R88 = RES: RES., OPTION, 1206; 4TH PART FIELD: VISHAY,; CLASS: DISCRETE; Case Size: 1206; FPLIST: CR1206N,CR1206L,CR1206M; PART_NUMBER: 100-2459; Package Size: 1206
R93 R94 = RES: RES.,5.1M OHMS,1%,1/4W,1206,ANTI-SULFUR,AEC-Q200; CLASS: DISCRETE; Inventory Qty: 0; Manufacturer: KOA SPEER; Manufacturer PN: RK73H2BRTTD5104F; PART_NUMBER: 100-1863; Package Size: 1206; Rated Power: 1/4W; Temperature Coefficient: +/-200ppm; Tolerance: 1%
RISO1 RISO2 = RES: RES.,0 OHM,1/4W,1206,AEC-Q200; 4TH PART FIELD: VISHAY,; CLASS: DISCRETE; FPLIST: CR1206N,CR1206L,CR1206M; Inventory Qty: 36327; Manufacturer: VISHAY; Manufacturer PN: CRCW12060000Z0EA; PART_NUMBER: 100-0200; Package Size: 1206; Rated Power: 1/4W
RISO3 = RES: RES., OPTION, 1206; CLASS: DISCRETE; Case Size: 1206; FPLIST: CR1206N,CR1206L,CR1206M; PART_NUMBER: 100-2459; Package Size: 1206
TP30 = testpad-2smd_6
TP31 = testpad-2smd
TP32 = testpad-2smd_1: TESTPOINT, PCB COPPER FEATURE; CLASS: IO
U1 = LTC3639-EMSE: IC,150V,100A,Synch.Step-Down Reg.,MSOP-16; CLASS: IC; Inventory Qty: 63; Manufacturer: ANALOG DEVICES; Manufacturer PN: LTC3639EMSE#PBF; PART_NUMBER: LTC3639EMSE#PBF; Package Type: MSOP-16

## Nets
Agnd: C8.1 C9.1 C15.1 C18.1 C24.1 C25.1 C26.1 C27.1 C33.1 D38.1(C) D39.3 D40.3 D41.3 D42.1(C) E23.1 E24.1 E25.1 E26.1 E70.1 E98.1 E99.1 F5.1 J6.27 J12.1 J13.23 J14.23 J15.23 J16.15 LED29.2(ANODE) MOV1.1 R24.2 R28.2 R93.1 RZZ3.2 RZZ4.2 RZZ7.2 RZZ8.2 RZZ11.2 RZZ12.2 RZZ15.2 RZZ16.2 RZZ17.2 RZZ19.2 RZZ21.2 RZZ23.2 RZZ25.2 RZZ27.2 RZZ29.2 RZZ31.2 TP31.1 TP32.1 U1.3(VIN) ; also on sheet 6 7 8 9 11 12
GND: C5.2 C11.1 C12.1 C13.2 C28.1 C29.1 C30.1 C32.1 C33.2 D31.2(A) E19.1 E20.1 J1.3 J1.8 J1.13 J2.3 J2.8 J2.13 J5.8 J6.15 J11.16 JP15.3 JP20.3 JP21.3 JP22.3 LED13.1(CATHODE) MOV1.2 R71.2 R92.2 R94.2 RISO2.1 RISO3.1 SW1.1 SW5.3 SW5.4 TP32.2
VDD: C5.1 C11.2 C12.2 C29.2 C30.2 D31.1(C) E18.1 J5.1 J6.5 J11.6 JP14.1 JP15.1 JP16.1 JP20.1 JP21.1 JP22.1 R1.1 R2.1 R4.2 R16.1 R17.1 R47.2 R48.1 R51.1 R52.1 R70.1 R91.1 RISO1.1
VEE: C6.2 C7.2 C15.2 C16.2 C17.2 C18.2 C24.2 C25.2 C26.2 C27.2 C32.2 D38.2(A) D39.1 D39.2 D40.1 D40.2 D41.1 D41.2 D42.2(A) E69.1 E100.1 F6.1 J6.28 J12.3 J12.5 J12.7 J12.9 J13.3 J13.5 J13.7 J13.9 J13.15 J13.17 J13.19 J13.21 J14.3 J14.5 J14.7 J14.9 J14.15 J14.17 J14.19 J14.21 J15.3 J15.5 J15.7 J15.9 J15.15 J15.17 J15.19 J15.21 J16.7 J16.9 J16.11 J16.13 R27.1 R29.1 R49.1 RISO2.2 RM1.2 RM2.2 RM3.2 RM4.2 RM5.2 RM6.2 RM7.2 RM8.2 RM9.2 RM10.2 RM11.2 RM12.2 RM13.2 RM14.2 RM15.2 RM16.2 RM17.2 RM18.2 RM19.2 RM20.2 RM21.2 RM22.2 RM23.2 RM24.2 RM25.2 RM26.2 RM27.2 RM28.2 RM29.2 RM30.2 RM31.2 RM32.2 TP30.1 U1.5(FBO) U1.7(VPRG1) U1.8(GND) U1.16(GND) U1.17(GND) ; also on sheet 11 12
4PVALID#: J6.11 JP14.2 R86.2
AD2: J6.16 R81.1 SW5.2
AD3: J6.13 R87.2 SW5.1
AUTO: J6.1 JP16.2 R53.2 R82.2
BUCK33: C17.1 E95.1 L1.2 R88.2 RISO1.2 U1.9(VFB)
CFG0: J5.7 J6.12 JP20.2 R79.1
CFG1: J5.13 J6.14 JP21.2 R80.1
CFG2: J5.5 J6.9 JP22.2 R85.2
CGND: C6.1 C7.1 C8.2 C9.2 CA1.2 CA2.2 CA3.2 CA4.2 CA5.2 CA6.2 CA7.2 CA8.2 CB1.2 CB2.2 CB3.2 CB4.2 CB5.2 CB6.2 CB7.2 CB8.2 J4.121 J4.122 J4.123 J4.127 J4.128 J4.129 RISO3.2 TP30.2 ; also on sheet 6 7 8 9
INT#: E10.1(A) J6.8 LED14.1(CATHODE) R77.1
MSD#: J6.3 R54.2 R83.2 R91.2 R92.1
OUT1: J12.2 RZZ1.2 ; also on sheet 12
OUT2: J12.4 RZZ2.2 ; also on sheet 12
OUT3: J12.6 RZZ5.2 ; also on sheet 12
OUT4: J12.8 RZZ6.2 ; also on sheet 12
OUT5: J12.10 RZZ13.2 ; also on sheet 12
OUT6: J12.12 RZZ14.2 ; also on sheet 12
OUT7: J13.2 RZZ9.2 ; also on sheet 12
OUT8: J13.4 RZZ10.2 ; also on sheet 12
OUT9: J13.6 RZZ24.2 ; also on sheet 12
OUT10: J13.8 RZZ22.2 ; also on sheet 12
OUT11: J13.10 RZZ20.2 ; also on sheet 12
OUT12: J13.12 RZZ18.2 ; also on sheet 12
OUT13: J13.14 RZZ32.2 ; also on sheet 12
OUT14: J13.16 RZZ30.2 ; also on sheet 12
OUT15: J13.18 RZZ28.2 ; also on sheet 12
OUT16: J13.20 RZZ26.2 ; also on sheet 12
OUT17: J13.22 ; also on sheet 6 12
OUT18: J13.24 ; also on sheet 6 12
OUT19: J14.2 ; also on sheet 6 12
OUT20: J14.4 ; also on sheet 6 12
OUT21: J14.6 ; also on sheet 6 12
OUT22: J14.8 ; also on sheet 6 12
OUT23: J14.10 ; also on sheet 6 12
OUT24: J14.12 ; also on sheet 6 12
OUT25: J14.14 ; also on sheet 7 11
OUT26: J14.16 ; also on sheet 7 11
OUT27: J14.18 ; also on sheet 7 11
OUT28: J14.20 ; also on sheet 7 11
OUT29: J14.22 ; also on sheet 7 11
OUT30: J14.24 ; also on sheet 7 11
OUT31: J15.2 ; also on sheet 7 11
OUT32: J15.4 ; also on sheet 7 11
OUT33: J15.6 ; also on sheet 8 11
OUT34: J15.8 ; also on sheet 8 11
OUT35: J15.10 ; also on sheet 8 11
OUT36: J15.12 ; also on sheet 8 11
OUT37: J15.14 ; also on sheet 8 11
OUT38: J15.16 ; also on sheet 8 11
OUT39: J15.18 ; also on sheet 8 11
OUT40: J15.20 ; also on sheet 8 11
OUT41: J15.22 ; also on sheet 9 11
OUT42: J15.24 ; also on sheet 9 11
OUT43: J16.6 ; also on sheet 9 11
OUT44: J16.8 ; also on sheet 9 11
OUT45: J16.10 ; also on sheet 9 11
OUT46: J16.12 ; also on sheet 9 11
OUT47: J16.14 ; also on sheet 9 11
OUT48: J16.16 ; also on sheet 9 11
PIN4: J5.9 J6.7 R84.2
PIN57-1: J6.19 R96.1
PIN57-2: J6.21 R98.1
PIN57-3: J6.23 R100.1
PIN57-4: J6.25 R102.1
PWRMD-1: J6.20 R64.2 R95.1
PWRMD-2: J6.22 R72.2 R97.1
PWRMD-3: J6.24 R89.2 R99.1
PWRMD-4: J6.26 R90.2 R101.1
RESET#: C28.2 E4.1(A) J6.2 R51.2 R74.1 SW1.2
SCL: E6.1(A) J1.4 J2.4 J6.10 R16.2 R78.1
SDAIN: E7.1(A) J1.14 J2.14 J6.4 R17.2 R73.2 R75.1
SDAOUT: E56.1(A) J1.7 J2.7 J6.6 R48.2 R73.1 R76.1
VL33: J13.1 J14.1 J15.1 J16.2 R88.1
N19720488: RO1.1 T1.10(TD_D)
N19720490: RP1.1 T1.7(TD_C)
N19720494: RQ1.1 T1.4(TD_B)
N19720496: RR1.1 T1.1(TD_A)
N19720513: RZ1.2 RZZ2.1 T1.24(TX_A)
N19720517: J4.108 T1.23(X+_A)
N19720523: J4.105 T1.20(X+_B)
N19720525: J4.102 T1.14(X+_D)
N19720527: CB1.1 CW1.2 CX1.2 CY1.2 CZ1.2
N19720533: J4.103 T1.16(X-_C)
N19720543: J4.107 T1.22(X-_A)
N19720551: RY1.2 RZZ4.1 T1.21(TX_B)
N19720607: CW1.1 RW1.1
N19720609: CY1.1 RY1.1
N19720611: CX1.1 RX1.1
N19720613: CZ1.1 RZ1.1
N19720640: RW1.2 RZZ1.1 T1.15(TX_D)
N19720646: RX1.2 RZZ3.1 T1.18(TX_C)
N19720820: CA1.1 RO1.2 RP1.2 RQ1.2 RR1.2
N19807268: J4.101 T1.13(X-_D)
N19809992: J4.106 T1.17(X+_C)
N19811966: J4.104 T1.19(X-_B)
N19903728: J4.81 T3.13(X-_D)
N19903743: J4.82 T3.14(X+_D)
N19903760: J4.83 T3.16(X-_C)
N19903762: J4.86 T3.17(X+_C)
N19903777: CB3.1 CW3.2 CX3.2 CY3.2 CZ3.2
N19903819: RO3.1 T3.10(TD_D)
N19903821: RP3.1 T3.7(TD_C)
N19903823: RQ3.1 T3.4(TD_B)
N19903825: RR3.1 T3.1(TD_A)
N19903839: RZ3.2 RZZ14.1 T3.24(TX_A)
N19903841: J4.88 T3.23(X+_A)
N19903843: J4.85 T3.20(X+_B)
N19903866: J4.87 T3.22(X-_A)
N19903868: RY3.2 RZZ16.1 T3.21(TX_B)
N19903884: CW3.1 RW3.1
N19903886: CY3.1 RY3.1
N19903888: CX3.1 RX3.1
N19903890: CZ3.1 RZ3.1
N19903892: CA3.1 RO3.2 RP3.2 RQ3.2 RR3.2
N19903894: RW3.2 RZZ13.1 T3.15(TX_D)
N19903898: RX3.2 RZZ15.1 T3.18(TX_C)
N19903982: J4.84 T3.19(X-_B)
N19913205: J4.111 T2.13(X-_D)
N19913220: J4.112 T2.14(X+_D)
N19913237: J4.113 T2.16(X-_C)
N19913239: J4.116 T2.17(X+_C)
N19913254: CB2.1 CW2.2 CX2.2 CY2.2 CZ2.2
N19913296: RO2.1 T2.10(TD_D)
N19913298: RP2.1 T2.7(TD_C)
N19913300: RQ2.1 T2.4(TD_B)
N19913302: RR2.1 T2.1(TD_A)
N19913316: RZ2.2 RZZ6.1 T2.24(TX_A)
N19913318: J4.118 T2.23(X+_A)
N19913320: J4.115 T2.20(X+_B)
N19913343: J4.117 T2.22(X-_A)
N19913345: RY2.2 RZZ8.1 T2.21(TX_B)
N19913361: CW2.1 RW2.1
N19913363: CY2.1 RY2.1
N19913365: CZ2.1 RZ2.1
N19913367: CA2.1 RO2.2 RP2.2 RQ2.2 RR2.2
N19913369: RW2.2 RZZ5.1 T2.15(TX_D)
N19913373: RX2.2 RZZ7.1 T2.18(TX_C)
N19913375: CX2.1 RX2.1
N19913459: J4.114 T2.19(X-_B)
N19917651: J4.91 T4.13(X-_D)
N19917657: J4.92 T4.14(X+_D)
N19917683: J4.93 T4.16(X-_C)
N19917685: J4.96 T4.17(X+_C)
N19917700: CB4.1 CW4.2 CX4.2 CY4.2 CZ4.2
N19917736: RO4.1 T4.10(TD_D)
N19917738: RP4.1 T4.7(TD_C)
N19917740: RQ4.1 T4.4(TD_B)
N19917748: RR4.1 T4.1(TD_A)
N19917754: RZ4.2 RZZ10.1 T4.24(TX_A)
N19917764: J4.98 T4.23(X+_A)
N19917766: J4.95 T4.20(X+_B)
N19917789: J4.97 T4.22(X-_A)
N19917791: RY4.2 RZZ12.1 T4.21(TX_B)
N19917807: CW4.1 RW4.1
N19917809: CY4.1 RY4.1
N19917811: CX4.1 RX4.1
N19917815: CA4.1 RO4.2 RP4.2 RQ4.2 RR4.2
N19917817: RW4.2 RZZ9.1 T4.15(TX_D)
N19917821: RX4.2 RZZ11.1 T4.18(TX_C)
N19917905: J4.94 T4.19(X-_B)
N19951006: J4.61 T5.13(X-_D)
N19951012: J4.62 T5.14(X+_D)
N19951038: J4.63 T5.16(X-_C)
N19951040: J4.66 T5.17(X+_C)
N19951055: CB5.1 CW5.2 CX5.2 CY5.2 CZ5.2
N19951091: RO5.1 T5.10(TD_D)
N19951093: RP5.1 T5.7(TD_C)
N19951095: RQ5.1 T5.4(TD_B)
N19951103: RR5.1 T5.1(TD_A)
N19951109: RZ5.2 RZZ22.1 T5.24(TX_A)
N19951119: J4.68 T5.23(X+_A)
N19951121: J4.65 T5.20(X+_B)
N19951144: J4.67 T5.22(X-_A)
N19951146: RY5.2 RZZ21.1 T5.21(TX_B)
N19951162: CW5.1 RW5.1
N19951164: CY5.1 RY5.1
N19951166: CX5.1 RX5.1
N19951168: CZ5.1 RZ5.1
N19951170: CA5.1 RO5.2 RP5.2 RQ5.2 RR5.2
N19951172: RW5.2 RZZ24.1 T5.15(TX_D)
N19951176: RX5.2 RZZ23.1 T5.18(TX_C)
N19951260: J4.64 T5.19(X-_B)
N19956370: J4.71 T6.13(X-_D)
N19956384: J4.72 T6.14(X+_D)
N19956401: J4.73 T6.16(X-_C)
N19956412: J4.76 T6.17(X+_C)
N19956418: CB6.1 CW6.2 CX6.2 CY6.2 CZ6.2
N19956463: RO6.1 T6.10(TD_D)
N19956465: RP6.1 T6.7(TD_C)
N19956467: RQ6.1 T6.4(TD_B)
N19956469: RR6.1 T6.1(TD_A)
N19956481: RZ6.2 RZZ18.1 T6.24(TX_A)
N19956483: J4.78 T6.23(X+_A)
N19956493: J4.75 T6.20(X+_B)
N19956516: J4.77 T6.22(X-_A)
N19956518: RY6.2 RZZ17.1 T6.21(TX_B)
N19956534: CW6.1 RW6.1
N19956536: CY6.1 RY6.1
N19956538: CX6.1 RX6.1
N19956540: CZ6.1 RZ6.1
N19956544: RW6.2 RZZ20.1 T6.15(TX_D)
N19956548: RX6.2 RZZ19.1 T6.18(TX_C)
N19956632: J4.74 T6.19(X-_B)
N19965415: J4.41 T7.13(X-_D)
N19965429: J4.42 T7.14(X+_D)
N19965446: J4.43 T7.16(X-_C)
N19965457: J4.46 T7.17(X+_C)
N19965463: CB7.1 CW7.2 CX7.2 CY7.2 CZ7.2
N19965508: RO7.1 T7.10(TD_D)
N19965510: RP7.1 T7.7(TD_C)
N19965512: RQ7.1 T7.4(TD_B)
N19965514: RR7.1 T7.1(TD_A)
N19965526: RZ7.2 RZZ30.1 T7.24(TX_A)
N19965528: J4.48 T7.23(X+_A)
N19965538: J4.45 T7.20(X+_B)
N19965561: J4.47 T7.22(X-_A)
N19965563: RY7.2 RZZ29.1 T7.21(TX_B)
N19965579: CW7.1 RW7.1
N19965581: CY7.1 RY7.1
N19965583: CX7.1 RX7.1
N19965585: CZ7.1 RZ7.1
N19965587: CA7.1 RO7.2 RP7.2 RQ7.2 RR7.2
N19965589: RW7.2 RZZ32.1 T7.15(TX_D)
N19965593: RX7.2 RZZ31.1 T7.18(TX_C)
N19965677: J4.44 T7.19(X-_B)
N20002875: J4.51 T8.13(X-_D)
N20002889: J4.52 T8.14(X+_D)
N20002905: J4.53 T8.16(X-_C)
N20002916: J4.56 T8.17(X+_C)
N20002922: CB8.1 CW8.2 CX8.2 CY8.2 CZ8.2
N20002968: RO8.1 T8.10(TD_D)
N20002970: RP8.1 T8.7(TD_C)
N20002972: RQ8.1 T8.4(TD_B)
N20002982: RR8.1 T8.1(TD_A)
N20002988: RZ8.2 RZZ26.1 T8.24(TX_A)
N20002990: J4.58 T8.23(X+_A)
N20002998: J4.55 T8.20(X+_B)
N20003029: J4.57 T8.22(X-_A)
N20003031: RY8.2 RZZ25.1 T8.21(TX_B)
N20003047: CW8.1 RW8.1
N20003049: CY8.1 RY8.1
N20003051: CX8.1 RX8.1
N20003053: CZ8.1 RZ8.1
N20003055: CA8.1 RO8.2 RP8.2 RQ8.2 RR8.2
N20003057: RW8.2 RZZ28.1 T8.15(TX_D)
N20003061: RX8.2 RZZ27.1 T8.18(TX_C)
N20003145: J4.54 T8.19(X-_B)
N21773761: CZ4.1 RZ4.1
N22299843: J11.11 R79.2
N22299909: J11.13 R80.2
N22303039: J11.15 R81.2
N22357420: CA6.1 RO6.2 RP6.2 RQ6.2 RR6.2
N22364008: E3.1(A) J1.5 J2.5 R52.2 R53.1 R54.1 SW2.1
N22364041: C23.2 J1.12 TP29.2 U2.1(A0) U2.2(A1) U2.3(A2) U2.4(VSS)
N22364054: C23.1 J1.10 REP5.1 REP6.1 REP7.1 U2.8(VCC)
N22364068: J1.9 REP7.2 U2.5(SDA)
N22364072: J1.11 REP6.2 U2.6(SCL)
N22364117: LED14.2(ANODE) R2.2
N22369477: J11.5 R76.2
N22369480: J11.1 R74.2
N22369483: J11.3 R75.2
N22369533: J11.9 R78.2
N22369536: J11.7 R77.2
N22376269: JP15.2 R70.2 R71.1 SW2.2
N22514686: LED13.2(ANODE) R1.2
N22514716: R24.1 R26.2 U1.14(RUN)
N22514718: R26.1 R27.2 U1.12(OVLO)
N22514721: R28.1 R29.2 U1.11(ISET)
N22514732: C16.1 U1.6(VPRG2) U1.10(SS)
N22514763: F5.2 J7.1 J8.1
N22514784: F6.2 J9.1 J10.1
N22564391: E96.1(A) JP1.1 JP1.3 JP1.5 JP1.7 JP1.9 JP1.11 JP1.13 JP1.15 R64.1
N22594537: J11.2 R82.1
N22594540: J11.4 R83.1
N22594546: J11.8 R84.1
N22594549: J11.10 R85.1
N22594561: J11.12 R86.1
N22594564: J11.14 R87.1
N22714752: JP1.14 RM7.1
N22850813: C13.1 J2.2 R4.1
N22879140: JP1.10 RM5.1
N22879625: JP1.4 RM2.1
N22879632: JP1.6 RM3.1
N22880021: JP1.2 RM1.1
N22880205: JP1.12 RM6.1
N22880444: JP1.8 RM4.1
N22889556: REP5.2 TP29.1 U2.7(WP)
N22917690: L1.1 U1.1(SW)
N23159963: E101.1(A) JP18.1 JP18.3 JP18.5 JP18.7 JP18.9 JP18.11 JP18.13 JP18.15 R89.1
N23163539: E102.1(A) JP19.1 JP19.3 JP19.5 JP19.7 JP19.9 JP19.11 JP19.13 JP19.15 R90.1
N23166332: E97.1(A) JP17.1 JP17.3 JP17.5 JP17.7 JP17.9 JP17.11 JP17.13 JP17.15 R72.1
N23228765: JP1.16 RM8.1
N23229161: JP17.2 RM9.1
N23229173: JP17.4 RM10.1
N23229185: JP17.6 RM11.1
N23229197: JP17.8 RM12.1
N23229209: JP17.10 RM13.1
N23229221: JP17.12 RM14.1
N23229233: JP17.14 RM15.1
N23229245: JP17.16 RM16.1
N23229484: JP18.2 RM17.1
N23229496: JP18.4 RM18.1
N23229508: JP18.6 RM19.1
N23229520: JP18.8 RM20.1
N23229532: JP18.10 RM21.1
N23229544: JP18.12 RM22.1
N23229556: JP18.14 RM23.1
N23229568: JP18.16 RM24.1
N23229807: JP19.2 RM25.1
N23229819: JP19.4 RM26.1
N23229831: JP19.6 RM27.1
N23229843: JP19.8 RM28.1
N23229855: JP19.10 RM29.1
N23229867: JP19.12 RM30.1
N23229879: JP19.14 RM31.1
N23229891: JP19.16 RM32.1
N23291703: TP30.3 TP31.2
N23491707: R93.2 R94.1
N23556782: LED29.1(CATHODE) R49.2
N23559577: J13.13 R96.2
N23559615: J13.11 R95.2
N23559753: J14.13 R98.2
N23559756: J14.11 R97.2
N23559873: J15.11 R99.2
N23559876: J15.13 R100.2
N23559959: J16.1 R101.2
N23559962: J16.3 R102.2
N23821535: J1.2 R47.1

Not connected (* = marked no-connect by the designer): J1 1* 6*; J2 1* 6* 9* 10* 11* 12*; J4 124* 125* 126*; J5 2* 3* 4* 6* 10* 11* 12* 14* 15* 16* 17* 18* 19* 20*; J6 17 18 29 30; J12 11*; J16 4* 5*; JP14 3; JP16 3; T1 2(D+_A) 3(D-_A) 5(D+_B) 6(D-_B) 8(D+_C) 9(D-_C) 11(D+_D) 12(D-_D); T2 2(D+_A) 3(D-_A) 5(D+_B) 6(D-_B) 8(D+_C) 9(D-_C) 11(D+_D) 12(D-_D); T3 2(D+_A) 3(D-_A) 5(D+_B) 6(D-_B) 8(D+_C) 9(D-_C) 11(D+_D) 12(D-_D); T4 2(D+_A) 3(D-_A) 5(D+_B) 6(D-_B) 8(D+_C) 9(D-_C) 11(D+_D) 12(D-_D); T5 2(D+_A) 3(D-_A) 5(D+_B) 6(D-_B) 8(D+_C) 9(D-_C) 11(D+_D) 12(D-_D); T6 2(D+_A) 3(D-_A) 5(D+_B) 6(D-_B) 8(D+_C) 9(D-_C) 11(D+_D) 12(D-_D); T7 2(D+_A) 3(D-_A) 5(D+_B) 6(D-_B) 8(D+_C) 9(D-_C) 11(D+_D) 12(D-_D); T8 2(D+_A) 3(D-_A) 5(D+_B) 6(D-_B) 8(D+_C) 9(D-_C) 11(D+_D) 12(D-_D); U1 2(NC)* 4(NC)* 13(NC)* 15(NC)*

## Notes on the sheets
sheet 1
- REVISION HISTORY
- POWER SUPPLY
- ECO
- REV
- DESCRIPTION
- APPROVED
- DATE
- 3
- OPTIONAL OVERCURRENT, OVERVOLTAGE,
  AND REVERSE VOLTAGE PROTECTION
- MAIN SUPPLY INPUT
- OPTIONAL
- AGND
- OPTIONAL LOCAL BUCK REGULATOR
- ISOLATION
- NOTE 3.
- BUCK33
- POS INPUT
- BANANA PLUG
- VDD
- (UP TO 15A)
- (3.3V)
- (3.3V/100mA)
- (UP TO 50A)
- TYPE 3: 51V - 57V
- TYPE 4: 53V - 57V
- DGND
- BUCK ON   11.4V
- BUCK OFF  10.4V
- (UP TO 50A)
- NEG INPUT
- VEE
- BANANA PLUG
- (UP TO 15A)
- VEE
- OPTIONAL SURGE PROTECTION
   AND BLEEDER RESISTANCE
- OPTIONAL ISOLATION
- NOTE 4.
- AGND
- AGND
- AGND
- AGND
- AGND
- AGND
- DGND
- MOV1
- V14E385P
- NOTE: UNLESS OTHERWISE SPECIFIED
- 1.  ALL RESISTORS AND CAPACITORS ARE 0603.
- 2.  INSTALL SHUNTS AS SHOWN.
- 3. REMOVE RESISTORS TO ISOLATE DIGITAL AND ANALOG DOMAINS
- 4. POPULATE RESISTOR TO CONNECT DIGITAL GROUND TO CHASSIS
sheet 2
- REVISION HISTORY
- CONFIGURATIONS
- ECO
- REV
- DESCRIPTION
- APPROVED
- DATE
- 3
- HI
- HI
- PWRMD-1
- LO
- LO
- PM0
- PM1
- OSS
- AD4
- PM2
- OSS
- PM3
- PM4
- RESET
- PM5
- PM6
- RESET
- PM7
- HI
- INT
- LO
- PWRMD-2
- SCL
- SDAIN
- PM0
- PM1
- ADDRESS
- PM2
- SDAOUT
- LO
- HI
- PM3
- PM4
- PM5
- PM6
- PM7
- PWRMD-3
- TO DC590
- I2C EXPANSION
- CFG0
- CFG1
- AD1
- HI
- HI
- HI
- PM0
- PM1
- LO
- LO
- LO
- PM2
- PM3
- PM4
- PM5
- PM6
- PM7
- PWRMD-4
- PM0
- PM1
- PM2
- PM3
- PM4
- PM5
- PM6
- PM7
- QUICKEVAL FOR DEMO ONLY
- ADI DEBUG
- NOTE: UNLESS OTHERWISE SPECIFIED
- 1.  ALL RESISTORS AND CAPACITORS ARE 0603.
- 2.  INSTALL SHUNTS AS SHOWN.
sheet 3
- REVISION HISTORY
- DAUGTHER CARD CONNECTIONS
- ECO
- REV
- DESCRIPTION
- APPROVED
- DATE
- 3
- DIGITAL CONNECTIONS
- ANALOG CONNECTIONS
- PORTS 1 - 3
- PORTS 4 - 9
- PK->
- PK->
- PORTS 22 - 24
- PORTS 10 - 15
- PORTS 16 - 21
- <-PK
- PK->
- NOTE: UNLESS OTHERWISE SPECIFIED
- 1.  ALL RESISTORS AND CAPACITORS ARE 0603.
- 2.  INSTALL SHUNTS AS SHOWN.
sheet 4
- REVISION HISTORY
- PORTS 1 - 4
- UPPER ROW
- ECO
- REV
- DESCRIPTION
- APPROVED
- DATE
- 3
- PoE OUT
- PoE OUT
- PORT 2
- PORT 4
- PoE OUT
- PoE OUT
- PORT 1
- PORT 3
- LOWER ROW
- NOTE: UNLESS OTHERWISE SPECIFIED
- 1.  ALL RESISTORS AND CAPACITORS ARE 0603.
- 2.  INSTALL SHUNTS AS SHOWN.
sheet 5
- REVISION HISTORY
- PORTS 5 - 8
- UPPER ROW
- ECO
- REV
- DESCRIPTION
- APPROVED
- DATE
- 3
- PoE OUT
- PoE OUT
- PORT 6
- PORT 8
- PoE OUT
- PoE OUT
- PORT 5
- PORT 7
- LOWER ROW
- NOTE: UNLESS OTHERWISE SPECIFIED
- 1.  ALL RESISTORS AND CAPACITORS ARE 0603.
- 2.  INSTALL SHUNTS AS SHOWN.
